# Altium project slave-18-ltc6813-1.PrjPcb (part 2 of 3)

## Sheet passive_balancing.SchDoc
size A3; SheetNumber: 5; SheetTotal: 15; SheetDescription: Passive Balancing
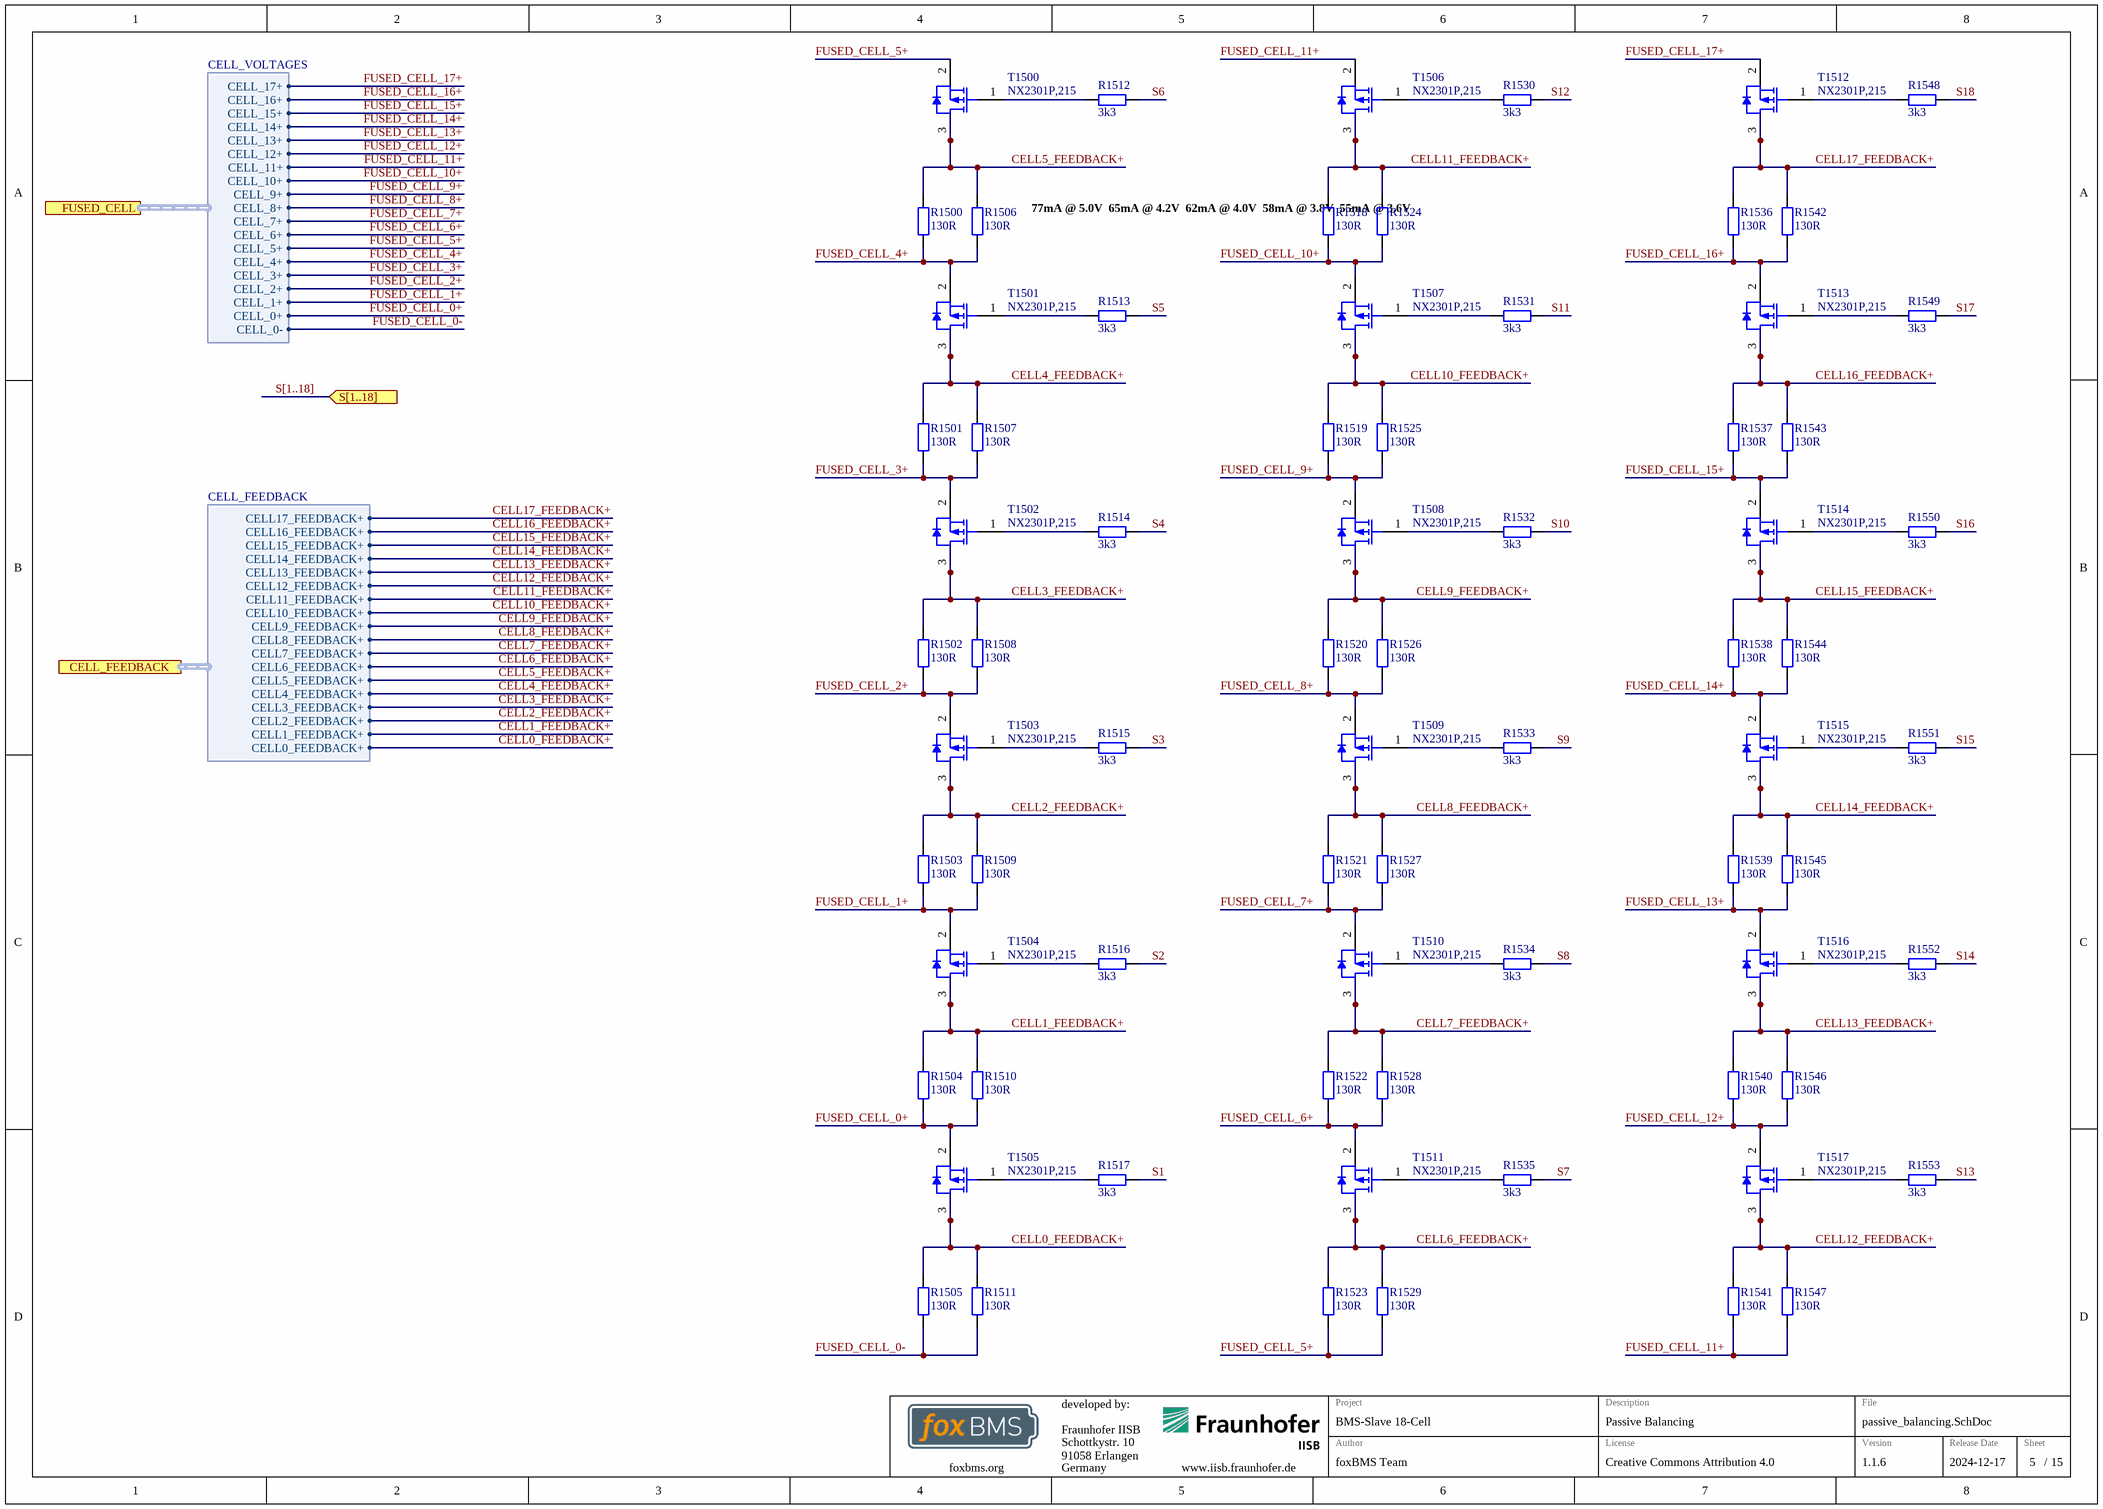
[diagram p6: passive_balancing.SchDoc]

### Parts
R1500  130R  [RESC5025X07N]
R1501  130R  [RESC5025X07N]
R1502  130R  [RESC5025X07N]
R1503  130R  [RESC5025X07N]
R1504  130R  [RESC5025X07N]
R1505  130R  [RESC5025X07N]
R1506  130R  [RESC5025X07N]
R1507  130R  [RESC5025X07N]
R1508  130R  [RESC5025X07N]
R1509  130R  [RESC5025X07N]
R1510  130R  [RESC5025X07N]
R1511  130R  [RESC5025X07N]
R1512  3k3  [RESC1608X05N]
R1513  3k3  [RESC1608X05N]
R1514  3k3  [RESC1608X05N]
R1515  3k3  [RESC1608X05N]
R1516  3k3  [RESC1608X05N]
R1517  3k3  [RESC1608X05N]
R1518  130R  [RESC5025X07N]
R1519  130R  [RESC5025X07N]
R1520  130R  [RESC5025X07N]
R1521  130R  [RESC5025X07N]
R1522  130R  [RESC5025X07N]
R1523  130R  [RESC5025X07N]
R1524  130R  [RESC5025X07N]
R1525  130R  [RESC5025X07N]
R1526  130R  [RESC5025X07N]
R1527  130R  [RESC5025X07N]
R1528  130R  [RESC5025X07N]
R1529  130R  [RESC5025X07N]
R1530  3k3  [RESC1608X05N]
R1531  3k3  [RESC1608X05N]
R1532  3k3  [RESC1608X05N]
R1533  3k3  [RESC1608X05N]
R1534  3k3  [RESC1608X05N]
R1535  3k3  [RESC1608X05N]
R1536  130R  [RESC5025X07N]
R1537  130R  [RESC5025X07N]
R1538  130R  [RESC5025X07N]
R1539  130R  [RESC5025X07N]
R1540  130R  [RESC5025X07N]
R1541  130R  [RESC5025X07N]
R1542  130R  [RESC5025X07N]
R1543  130R  [RESC5025X07N]
R1544  130R  [RESC5025X07N]
R1545  130R  [RESC5025X07N]
R1546  130R  [RESC5025X07N]
R1547  130R  [RESC5025X07N]
R1548  3k3  [RESC1608X05N]
R1549  3k3  [RESC1608X05N]
R1550  3k3  [RESC1608X05N]
R1551  3k3  [RESC1608X05N]
R1552  3k3  [RESC1608X05N]
R1553  3k3  [RESC1608X05N]
T1500  NX2301P,215  [NXP-SOT23_N]
T1501  NX2301P,215  [NXP-SOT23_N]
T1502  NX2301P,215  [NXP-SOT23_N]
T1503  NX2301P,215  [NXP-SOT23_N]
T1504  NX2301P,215  [NXP-SOT23_N]
T1505  NX2301P,215  [NXP-SOT23_N]
T1506  NX2301P,215  [NXP-SOT23_N]
T1507  NX2301P,215  [NXP-SOT23_N]
T1508  NX2301P,215  [NXP-SOT23_N]
T1509  NX2301P,215  [NXP-SOT23_N]
T1510  NX2301P,215  [NXP-SOT23_N]
T1511  NX2301P,215  [NXP-SOT23_N]
T1512  NX2301P,215  [NXP-SOT23_N]
T1513  NX2301P,215  [NXP-SOT23_N]
T1514  NX2301P,215  [NXP-SOT23_N]
T1515  NX2301P,215  [NXP-SOT23_N]
T1516  NX2301P,215  [NXP-SOT23_N]
T1517  NX2301P,215  [NXP-SOT23_N]

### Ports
CELL_FEEDBACK (harness CELL_FEEDBACK), FUSED_CELL (harness CELL_VOLTAGES), S[1..18] (in)

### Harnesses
CELL_FEEDBACK: CELL11_FEEDBACK+, CELL10_FEEDBACK+, CELL9_FEEDBACK+, CELL8_FEEDBACK+, CELL7_FEEDBACK+, CELL6_FEEDBACK+, CELL5_FEEDBACK+, CELL4_FEEDBACK+, CELL3_FEEDBACK+, CELL2_FEEDBACK+, CELL1_FEEDBACK+, CELL0_FEEDBACK+, CELL12_FEEDBACK+, CELL13_FEEDBACK+, CELL14_FEEDBACK+, CELL15_FEEDBACK+, CELL16_FEEDBACK+, CELL17_FEEDBACK+
CELL_VOLTAGES: CELL_0-, CELL_0+, CELL_1+, CELL_10+, CELL_11+, CELL_12+, CELL_13+, CELL_14+, CELL_15+, CELL_16+, CELL_17+, CELL_2+, CELL_3+, CELL_4+, CELL_5+, CELL_6+, CELL_7+, CELL_8+, CELL_9+

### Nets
CELL0_FEEDBACK+: R1505.2 R1511.2 T1505.3(D) ; port CELL_FEEDBACK.CELL0_FEEDBACK+  [project net CELL_FEEDBACK.CELL0_FEEDBACK+]
CELL1_FEEDBACK+: R1504.2 R1510.2 T1504.3(D) ; port CELL_FEEDBACK.CELL1_FEEDBACK+  [project net CELL_FEEDBACK.CELL1_FEEDBACK+]
CELL2_FEEDBACK+: R1503.2 R1509.2 T1503.3(D) ; port CELL_FEEDBACK.CELL2_FEEDBACK+  [project net CELL_FEEDBACK.CELL2_FEEDBACK+]
CELL3_FEEDBACK+: R1502.2 R1508.2 T1502.3(D) ; port CELL_FEEDBACK.CELL3_FEEDBACK+  [project net CELL_FEEDBACK.CELL3_FEEDBACK+]
CELL4_FEEDBACK+: R1501.2 R1507.2 T1501.3(D) ; port CELL_FEEDBACK.CELL4_FEEDBACK+  [project net CELL_FEEDBACK.CELL4_FEEDBACK+]
CELL5_FEEDBACK+: R1500.2 R1506.2 T1500.3(D) ; port CELL_FEEDBACK.CELL5_FEEDBACK+  [project net CELL_FEEDBACK.CELL5_FEEDBACK+]
CELL6_FEEDBACK+: R1523.2 R1529.2 T1511.3(D) ; port CELL_FEEDBACK.CELL6_FEEDBACK+  [project net CELL_FEEDBACK.CELL6_FEEDBACK+]
CELL7_FEEDBACK+: R1522.2 R1528.2 T1510.3(D) ; port CELL_FEEDBACK.CELL7_FEEDBACK+  [project net CELL_FEEDBACK.CELL7_FEEDBACK+]
CELL8_FEEDBACK+: R1521.2 R1527.2 T1509.3(D) ; port CELL_FEEDBACK.CELL8_FEEDBACK+  [project net CELL_FEEDBACK.CELL8_FEEDBACK+]
CELL9_FEEDBACK+: R1520.2 R1526.2 T1508.3(D) ; port CELL_FEEDBACK.CELL9_FEEDBACK+  [project net CELL_FEEDBACK.CELL9_FEEDBACK+]
CELL10_FEEDBACK+: R1519.2 R1525.2 T1507.3(D) ; port CELL_FEEDBACK.CELL10_FEEDBACK+  [project net CELL_FEEDBACK.CELL10_FEEDBACK+]
CELL11_FEEDBACK+: R1518.2 R1524.2 T1506.3(D) ; port CELL_FEEDBACK.CELL11_FEEDBACK+  [project net CELL_FEEDBACK.CELL11_FEEDBACK+]
CELL12_FEEDBACK+: R1541.2 R1547.2 T1517.3(D) ; port CELL_FEEDBACK.CELL12_FEEDBACK+  [project net CELL_FEEDBACK.CELL12_FEEDBACK+]
CELL13_FEEDBACK+: R1540.2 R1546.2 T1516.3(D) ; port CELL_FEEDBACK.CELL13_FEEDBACK+  [project net CELL_FEEDBACK.CELL13_FEEDBACK+]
CELL14_FEEDBACK+: R1539.2 R1545.2 T1515.3(D) ; port CELL_FEEDBACK.CELL14_FEEDBACK+  [project net CELL_FEEDBACK.CELL14_FEEDBACK+]
CELL15_FEEDBACK+: R1538.2 R1544.2 T1514.3(D) ; port CELL_FEEDBACK.CELL15_FEEDBACK+  [project net CELL_FEEDBACK.CELL15_FEEDBACK+]
CELL16_FEEDBACK+: R1537.2 R1543.2 T1513.3(D) ; port CELL_FEEDBACK.CELL16_FEEDBACK+  [project net CELL_FEEDBACK.CELL16_FEEDBACK+]
CELL17_FEEDBACK+: R1536.2 R1542.2 T1512.3(D) ; port CELL_FEEDBACK.CELL17_FEEDBACK+  [project net CELL_FEEDBACK.CELL17_FEEDBACK+]
FUSED_CELL_0+: R1504.1 R1510.1 T1505.2(S) ; port FUSED_CELL.CELL_0+  [project net FUSED_CELL.CELL_0+]
FUSED_CELL_0-: R1505.1 R1511.1 ; port FUSED_CELL.CELL_0-  [project net FUSED_CELL.CELL_0-]
FUSED_CELL_1+: R1503.1 R1509.1 T1504.2(S) ; port FUSED_CELL.CELL_1+  [project net FUSED_CELL.CELL_1+]
FUSED_CELL_2+: R1502.1 R1508.1 T1503.2(S) ; port FUSED_CELL.CELL_2+  [project net FUSED_CELL.CELL_2+]
FUSED_CELL_3+: R1501.1 R1507.1 T1502.2(S) ; port FUSED_CELL.CELL_3+  [project net FUSED_CELL.CELL_3+]
FUSED_CELL_4+: R1500.1 R1506.1 T1501.2(S) ; port FUSED_CELL.CELL_4+  [project net FUSED_CELL.CELL_4+]
FUSED_CELL_5+: R1523.1 R1529.1 T1500.2(S) ; port FUSED_CELL.CELL_5+  [project net FUSED_CELL.CELL_5+]
FUSED_CELL_6+: R1522.1 R1528.1 T1511.2(S) ; port FUSED_CELL.CELL_6+  [project net FUSED_CELL.CELL_6+]
FUSED_CELL_7+: R1521.1 R1527.1 T1510.2(S) ; port FUSED_CELL.CELL_7+  [project net FUSED_CELL.CELL_7+]
FUSED_CELL_8+: R1520.1 R1526.1 T1509.2(S) ; port FUSED_CELL.CELL_8+  [project net FUSED_CELL.CELL_8+]
FUSED_CELL_9+: R1519.1 R1525.1 T1508.2(S) ; port FUSED_CELL.CELL_9+  [project net FUSED_CELL.CELL_9+]
FUSED_CELL_10+: R1518.1 R1524.1 T1507.2(S) ; port FUSED_CELL.CELL_10+  [project net FUSED_CELL.CELL_10+]
FUSED_CELL_11+: R1541.1 R1547.1 T1506.2(S) ; port FUSED_CELL.CELL_11+  [project net FUSED_CELL.CELL_11+]
FUSED_CELL_12+: R1540.1 R1546.1 T1517.2(S) ; port FUSED_CELL.CELL_12+  [project net FUSED_CELL.CELL_12+]
FUSED_CELL_13+: R1539.1 R1545.1 T1516.2(S) ; port FUSED_CELL.CELL_13+  [project net FUSED_CELL.CELL_13+]
FUSED_CELL_14+: R1538.1 R1544.1 T1515.2(S) ; port FUSED_CELL.CELL_14+  [project net FUSED_CELL.CELL_14+]
FUSED_CELL_15+: R1537.1 R1543.1 T1514.2(S) ; port FUSED_CELL.CELL_15+  [project net FUSED_CELL.CELL_15+]
FUSED_CELL_16+: R1536.1 R1542.1 T1513.2(S) ; port FUSED_CELL.CELL_16+  [project net FUSED_CELL.CELL_16+]
FUSED_CELL_17+: T1512.2(S) ; port FUSED_CELL.CELL_17+  [project net FUSED_CELL.CELL_17+]
S1: R1517.2  [project net PRIMARY-S1]
S2: R1516.2  [project net PRIMARY-S2]
S3: R1515.2  [project net PRIMARY-S3]
S4: R1514.2  [project net PRIMARY-S4]
S5: R1513.2  [project net PRIMARY-S5]
S6: R1512.2  [project net PRIMARY-S6]
S7: R1535.2  [project net PRIMARY-S7]
S8: R1534.2  [project net PRIMARY-S8]
S9: R1533.2  [project net PRIMARY-S9]
S10: R1532.2  [project net PRIMARY-S10]
S11: R1531.2  [project net PRIMARY-S11]
S12: R1530.2  [project net PRIMARY-S12]
S13: R1553.2  [project net PRIMARY-S13]
S14: R1552.2  [project net PRIMARY-S14]
S15: R1551.2  [project net PRIMARY-S15]
S16: R1550.2  [project net PRIMARY-S16]
S17: R1549.2  [project net PRIMARY-S17]
S18: R1548.2  [project net PRIMARY-S18]
NetR1512_1: R1512.1 T1500.1(G)
NetR1513_1: R1513.1 T1501.1(G)
NetR1514_1: R1514.1 T1502.1(G)
NetR1515_1: R1515.1 T1503.1(G)
NetR1516_1: R1516.1 T1504.1(G)
NetR1517_1: R1517.1 T1505.1(G)
NetR1530_1: R1530.1 T1506.1(G)
NetR1531_1: R1531.1 T1507.1(G)
NetR1532_1: R1532.1 T1508.1(G)
NetR1533_1: R1533.1 T1509.1(G)
NetR1534_1: R1534.1 T1510.1(G)
NetR1535_1: R1535.1 T1511.1(G)
NetR1548_1: R1548.1 T1512.1(G)
NetR1549_1: R1549.1 T1513.1(G)
NetR1550_1: R1550.1 T1514.1(G)
NetR1551_1: R1551.1 T1515.1(G)
NetR1552_1: R1552.1 T1516.1(G)
NetR1553_1: R1553.1 T1517.1(G)

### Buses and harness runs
bus S[1..18] = port S[1..18]

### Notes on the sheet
- 77mA @ 5.0V
  65mA @ 4.2V
  62mA @ 4.0V
  58mA @ 3.8V
  55mA @ 3.6V

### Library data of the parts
R1500-R1511 R1518-R1529 R1536-R1547 = gen_R_130R_2010: SMD Resistor 130R 2010; Tolerance: 5%; Power: 0.75W; Case EIA: 2010; Case Metric: 5025; Maximum Working Voltage: 400V; PnP Package: R_2010; Automotive Qualified: True
R1512-R1517 R1530-R1535 R1548-R1553 = gen_R_3k3_0603: SMD Resistor 3k3 0603; Tolerance: 1%; Power: 0.1W; Case EIA: 0603; Case Metric: 1608; Maximum Working Voltage: 75V; PnP Package: R_0603; Automotive Qualified: True
T1500-T1517 = CMP-1259-00090-1: P-Channel Trench MOSFET, -20 V, -2 A, -55 to 150 degC, 3-Pin SOT23, Tape and Reel; Manufacturer: NXP Semiconductors; VGSth [typ] (V): -0.75; Channel Type: P; Packing: Tape & Reel; Automotive Qualified: Y; IDM [max] (A): -6

## Sheet LTC.SchDoc
size A3; SheetNumber: 2; SheetTotal: 15; SheetDescription: LTC6813
Used 2 times, as channels U_primary_LTC, U_secondary_LTC. Parts and nets are listed once, with the designators drawn on the sheet.
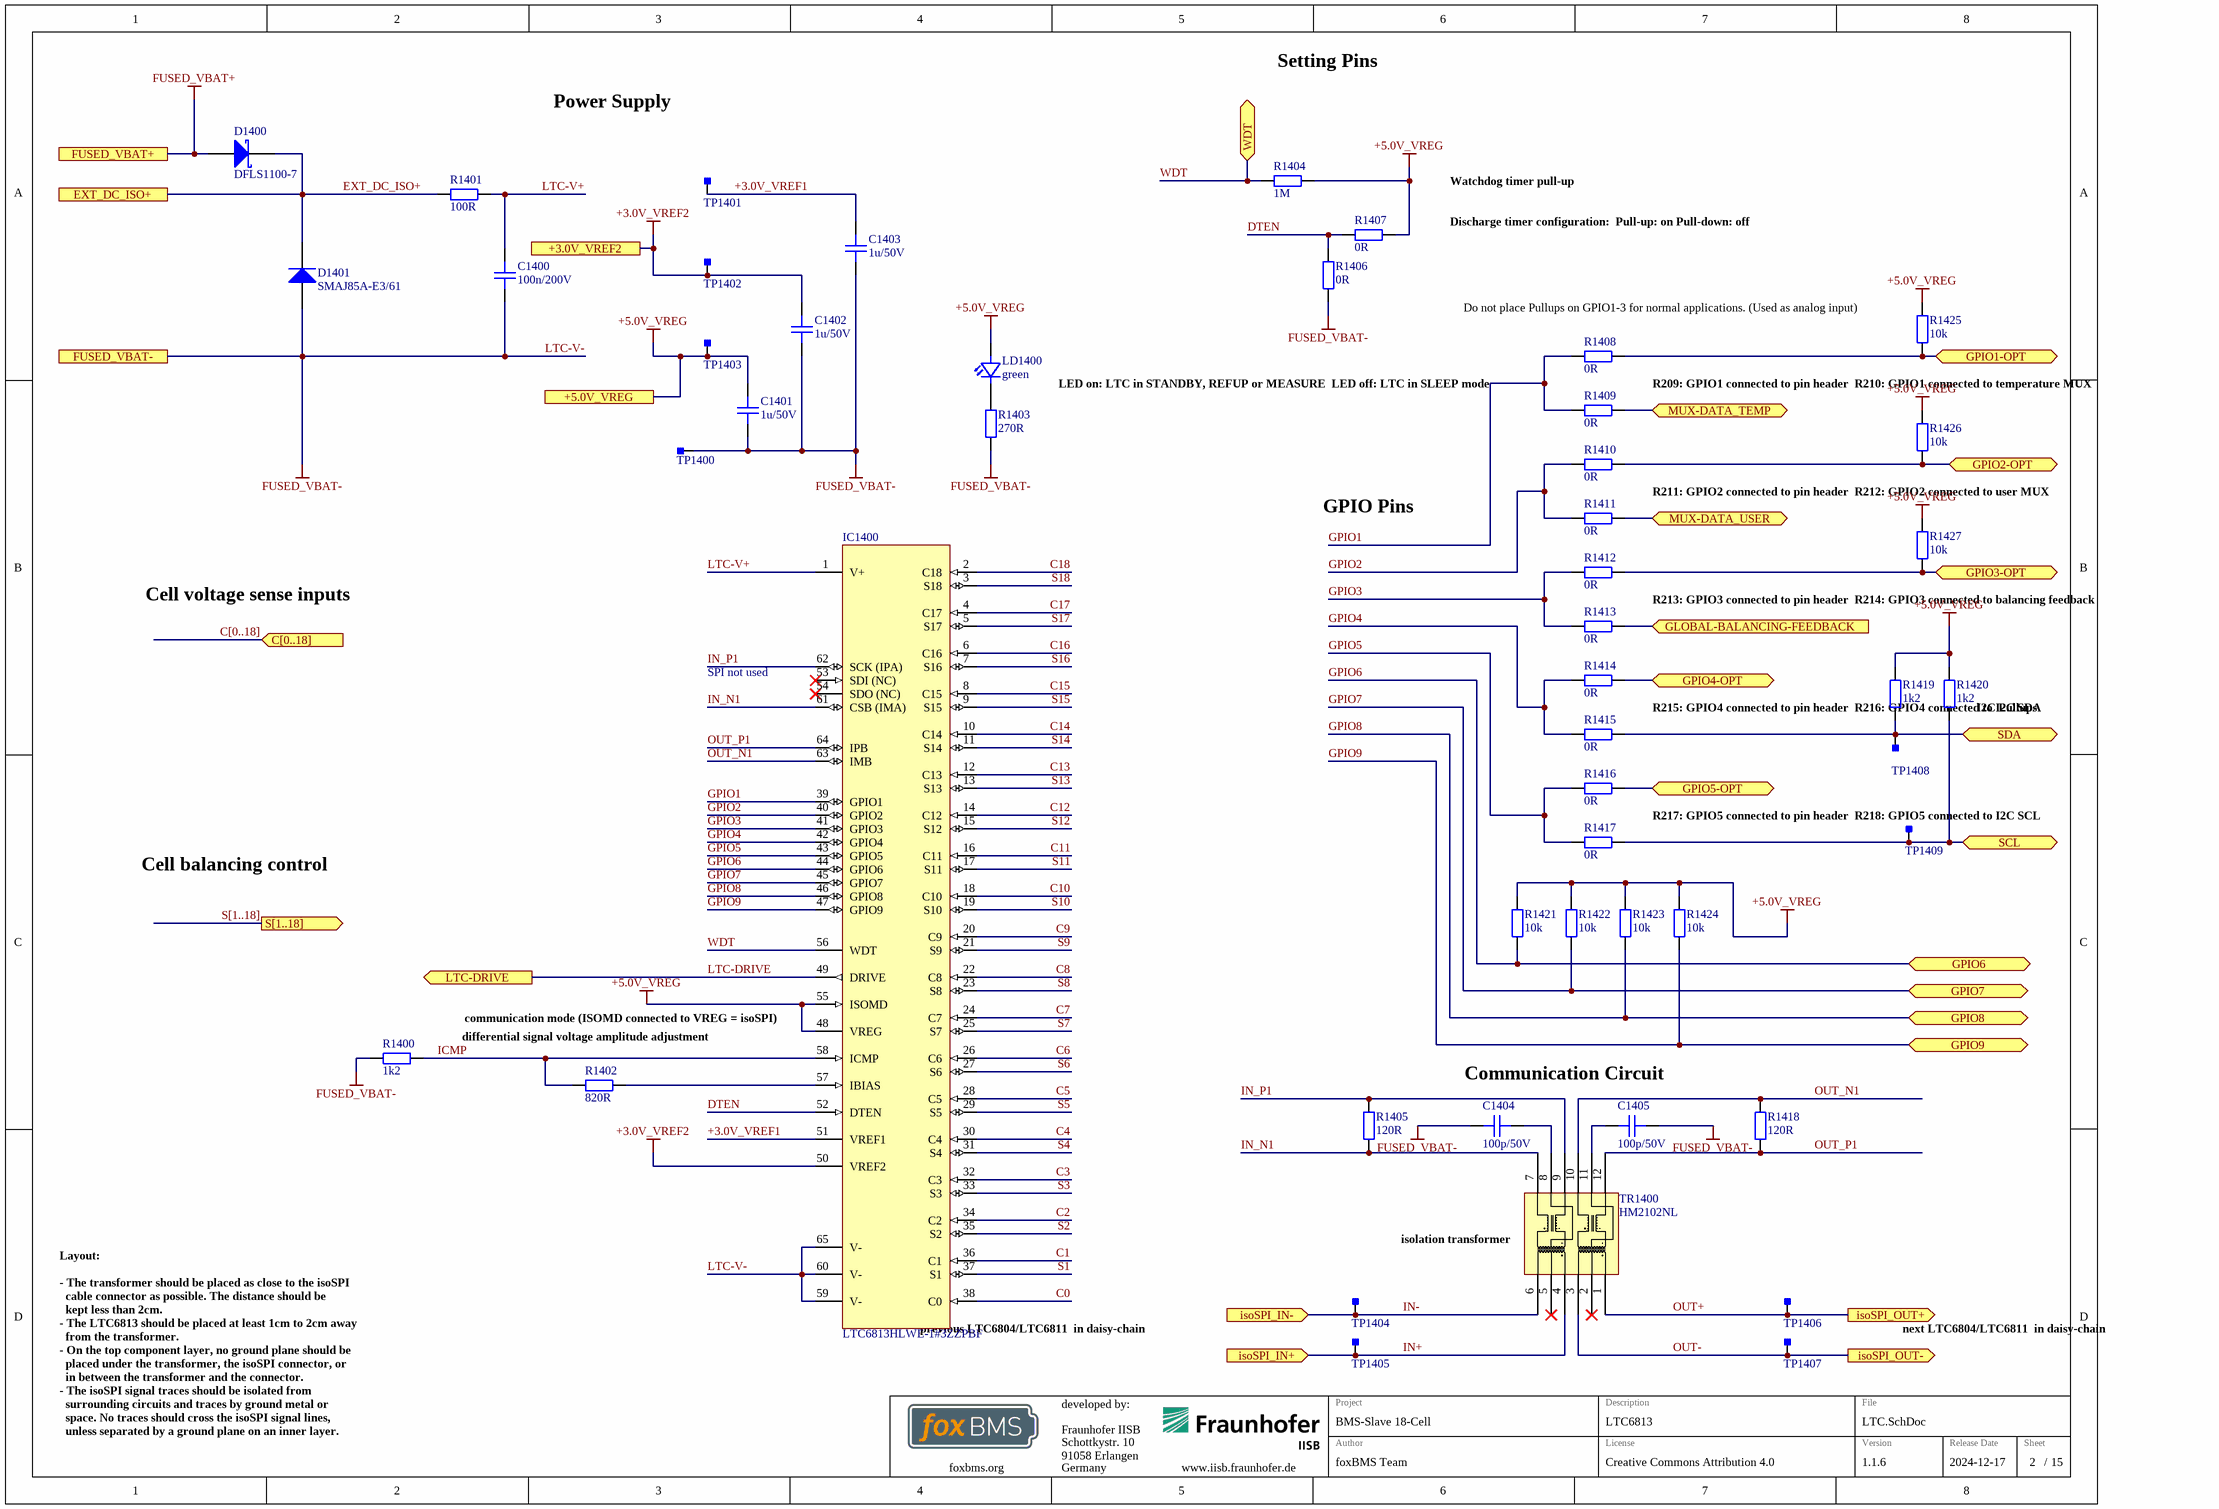
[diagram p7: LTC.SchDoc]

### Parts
C1400  100n/200V  [CAPC3216X18N]
C1401  1u/50V  [CAPC2012X14N]
C1402  1u/50V  [CAPC2012X14N]
C1403  1u/50V  [CAPC2012X14N]
C1404  100p/50V  [CAPC1608X08N]
C1405  100p/50V  [CAPC1608X08N]
D1400  DFLS1100-7  [DIOD-POWERDI123-2_V]
D1401  SMAJ85A-E3/61  [VISH-DO-214AC-2_L]
IC1400  LTC6813HLWE-1#3ZZPBF  [TSQFP50P1200X1200X160_HS-65N]
LD1400  green  [LEDC1608X07N]
R1400  1k2  [RESC1608X05N]
R1401  100R  [RESC2012X05N]
R1402  820R  [RESC1608X05N]
R1403  270R  [RESC1608X05N]
R1404  1M  [RESC1608X05N]
R1405  120R  [RESC1608X05N]
R1406  0R  [RESC1608X05N]
R1407  0R  [RESC1608X05N]
R1408  0R  [RESC1608X05N]
R1409  0R  [RESC1608X05N]
R1410  0R  [RESC1608X05N]
R1411  0R  [RESC1608X05N]
R1412  0R  [RESC1608X05N]
R1413  0R  [RESC1608X05N]
R1414  0R  [RESC1608X05N]
R1415  0R  [RESC1608X05N]
R1416  0R  [RESC1608X05N]
R1417  0R  [RESC1608X05N]
R1418  120R  [RESC1608X05N]
R1419  1k2  [RESC1608X05N]
R1420  1k2  [RESC1608X05N]
R1421  10k  [RESC1608X05N]
R1422  10k  [RESC1608X05N]
R1423  10k  [RESC1608X05N]
R1424  10k  [RESC1608X05N]
R1425  10k  [RESC1608X05N]
R1426  10k  [RESC1608X05N]
R1427  10k  [RESC1608X05N]
TP1400  Testpoint_Square  [Testpoint_S1]  (value not drawn)  (no BOM)
TP1401  Testpoint_Square  [Testpoint_S1]  (value not drawn)  (no BOM)
TP1402  Testpoint_Square  [Testpoint_S1]  (value not drawn)  (no BOM)
TP1403  Testpoint_Square  [Testpoint_S1]  (value not drawn)  (no BOM)
TP1404  Testpoint_Square  [Testpoint_S1]  (value not drawn)  (no BOM)
TP1405  Testpoint_Square  [Testpoint_S1]  (value not drawn)  (no BOM)
TP1406  Testpoint_Square  [Testpoint_S1]  (value not drawn)  (no BOM)
TP1407  Testpoint_Square  [Testpoint_S1]  (value not drawn)  (no BOM)
TP1408  Testpoint_Square  [Testpoint_S1]  (value not drawn)  (no BOM)
TP1409  Testpoint_Square  [Testpoint_S1]  (value not drawn)  (no BOM)
TR1400  HM2102NL  [HM2102NL]

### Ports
+3.0V_VREF2, +5.0V_VREG, C[0..18] (in), EXT_DC_ISO+, FUSED_VBAT+, FUSED_VBAT-, GLOBAL-BALANCING-FEEDBACK (in), GPIO1-OPT (bidir), GPIO2-OPT (bidir), GPIO3-OPT (bidir), GPIO4-OPT (bidir), GPIO5-OPT (bidir), GPIO6 (bidir), GPIO7 (bidir), GPIO8 (bidir), GPIO9 (bidir), isoSPI_IN+ (in), isoSPI_IN- (in), isoSPI_OUT+ (out), isoSPI_OUT- (out), LTC-DRIVE (out), MUX-DATA_TEMP (bidir), MUX-DATA_USER (bidir), S[1..18] (out), SCL (bidir), SDA (bidir), WDT (bidir)

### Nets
+3.0V_VREF2: C1402.2 IC1400.50(VREF2) TP1402.1 ; port +3.0V_VREF2
+5.0V_VREG: C1401.2 IC1400.48(VREG) IC1400.55(ISOMD) LD1400.2(A) R1404.2 R1407.2 R1419.2 R1420.2 R1421.2 R1422.2 R1423.2 R1424.2 R1425.2 R1426.2 R1427.2 TP1403.1 ; port +5.0V_VREG
FUSED_VBAT+: D1400.1(A) ; port FUSED_VBAT+
FUSED_VBAT-: C1400.2 C1401.1 C1402.1 C1403.1 C1404.1 C1405.1 D1401.2(A) IC1400.59(V-) IC1400.60(V-) IC1400.65(V-) R1400.1 R1403.1 R1406.1 TP1400.1 ; port FUSED_VBAT-  [also labelled LTC-V-]
+3.0V_VREF1: C1403.2 IC1400.51(VREF1) TP1401.1
C0: IC1400.38(C0)
C1: IC1400.36(C1)
C2: IC1400.34(C2)
C3: IC1400.32(C3)
C4: IC1400.30(C4)
C5: IC1400.28(C5)
C6: IC1400.26(C6)
C7: IC1400.24(C7)
C8: IC1400.22(C8)
C9: IC1400.20(C9)
C10: IC1400.18(C10)
C11: IC1400.16(C11)
C12: IC1400.14(C12)
C13: IC1400.12(C13)
C14: IC1400.10(C14)
C15: IC1400.8(C15)
C16: IC1400.6(C16)
C17: IC1400.4(C17)
C18: IC1400.2(C18)
DTEN: IC1400.52(DTEN) R1406.2 R1407.1
EXT_DC_ISO+: D1400.2(K) D1401.1(K) R1401.1 ; port EXT_DC_ISO+
GLOBAL-BALANCING-FEEDBACK: R1413.1 ; port GLOBAL-BALANCING-FEEDBACK
GPIO1: IC1400.39(GPIO1) R1408.2 R1409.2
GPIO1-OPT: R1408.1 R1425.1 ; port GPIO1-OPT
GPIO2: IC1400.40(GPIO2) R1410.2 R1411.2
GPIO2-OPT: R1410.1 R1426.1 ; port GPIO2-OPT
GPIO3: IC1400.41(GPIO3) R1412.2 R1413.2
GPIO3-OPT: R1412.1 R1427.1 ; port GPIO3-OPT
GPIO4: IC1400.42(GPIO4) R1414.2 R1415.2
GPIO4-OPT: R1414.1 ; port GPIO4-OPT
GPIO5: IC1400.43(GPIO5) R1416.2 R1417.2
GPIO5-OPT: R1416.1 ; port GPIO5-OPT
GPIO6: IC1400.44(GPIO6) R1421.1 ; port GPIO6
GPIO7: IC1400.45(GPIO7) R1422.1 ; port GPIO7
GPIO8: IC1400.46(GPIO8) R1423.1 ; port GPIO8
GPIO9: IC1400.47(GPIO9) R1424.1 ; port GPIO9
ICMP: IC1400.58(ICMP) R1400.2 R1402.1
IN+: TP1405.1 TR1400.4 ; port isoSPI_IN+
IN-: TP1404.1 TR1400.6 ; port isoSPI_IN-
IN_N1: IC1400.61(CSB_(IMA)) R1405.2 TR1400.7
IN_P1: IC1400.62(SCK_(IPA)) R1405.1 TR1400.9
LTC-DRIVE: IC1400.49(DRIVE) ; port LTC-DRIVE
LTC-V+: C1400.1 IC1400.1(V+) R1401.2
MUX-DATA_TEMP: R1409.1 ; port MUX-DATA_TEMP
MUX-DATA_USER: R1411.1 ; port MUX-DATA_USER
OUT+: TP1406.1 TR1400.1 ; port isoSPI_OUT+
OUT-: TP1407.1 TR1400.3 ; port isoSPI_OUT-
OUT_N1: IC1400.63(IMB) R1418.2 TR1400.10
OUT_P1: IC1400.64(IPB) R1418.1 TR1400.12
S1: IC1400.37(S1)
S2: IC1400.35(S2)
S3: IC1400.33(S3)
S4: IC1400.31(S4)
S5: IC1400.29(S5)
S6: IC1400.27(S6)
S7: IC1400.25(S7)
S8: IC1400.23(S8)
S9: IC1400.21(S9)
S10: IC1400.19(S10)
S11: IC1400.17(S11)
S12: IC1400.15(S12)
S13: IC1400.13(S13)
S14: IC1400.11(S14)
S15: IC1400.9(S15)
S16: IC1400.7(S16)
S17: IC1400.5(S17)
S18: IC1400.3(S18)
SCL: R1417.1 R1420.1 TP1409.1 ; port SCL
SDA: R1415.1 R1419.1 TP1408.1 ; port SDA
WDT: IC1400.56(WDT) R1404.1 ; port WDT
NetC1404_2: C1404.2 TR1400.8
NetC1405_2: C1405.2 TR1400.11
NetIC1400_57: IC1400.57(IBIAS) R1402.2
NetLD1400_1: LD1400.1(C) R1403.2

Not connected (* = marked no-connect by the designer): IC1400 53(SDI_(NC))* 54(SDO_(NC))*; TR1400 2* 5*

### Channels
U_primary_LTC: designators end in _1; ports +3.0V_VREF2=+3.0V_VREF2 +5.0V_VREG=+5.0V_VREG EXT_DC_ISO+=EXT_DC_ISO+ FUSED_VBAT+=FUSED_VBAT+ FUSED_VBAT-=FUSED_VBAT- GLOBAL-BALANCING-FEEDBACK=GLOBAL-BAL-FB GPIO1-OPT=PRIMARY-GPIO1-OPT GPIO2-OPT=PRIMARY-GPIO2-OPT GPIO3-OPT=PRIMARY-GPIO3-OPT GPIO4-OPT=PRIMARY-GPIO4-OPT GPIO5-OPT=PRIMARY-GPIO5-OPT GPIO6=PRIMARY-GPIO6 GPIO7=PRIMARY-GPIO7 GPIO8=PRIMARY-GPIO8 GPIO9=PRIMARY-GPIO9 isoSPI_IN+=PRIMARY-IN+ isoSPI_IN-=PRIMARY-IN- isoSPI_OUT+=PRIMARY-OUT+ isoSPI_OUT-=PRIMARY-OUT- LTC-DRIVE=PRIMARY-LTC-DRIVE MUX-DATA_TEMP=PRIMARY-MUX-DATA_TEMP MUX-DATA_USER=PRIMARY-MUX-DATA_USER SCL=PRIMARY-SCL SDA=PRIMARY-SDA WDT=PRIMARY-WDT
U_secondary_LTC: designators end in _2; ports +3.0V_VREF2=+3.0V_VREF2 +5.0V_VREG=+5.0V_VREG EXT_DC_ISO+=EXT_DC_ISO+ FUSED_VBAT+=FUSED_VBAT+ FUSED_VBAT-=FUSED_VBAT- GLOBAL-BALANCING-FEEDBACK=GLOBAL-BAL-FB GPIO1-OPT=SECONDARY-GPIO1-OPT GPIO2-OPT=SECONDARY-GPIO2-OPT GPIO3-OPT=SECONDARY-GPIO3-OPT GPIO4-OPT=SECONDARY-GPIO4-OPT GPIO5-OPT=SECONDARY-GPIO5-OPT GPIO6=SECONDARY-GPIO6 GPIO7=SECONDARY-GPIO7 GPIO8=SECONDARY-GPIO8 GPIO9=SECONDARY-GPIO9 isoSPI_IN+=SECONDARY-IN+ isoSPI_IN-=SECONDARY-IN- isoSPI_OUT+=SECONDARY-OUT+ isoSPI_OUT-=SECONDARY-OUT- LTC-DRIVE=SECONDARY-LTC-DRIVE MUX-DATA_TEMP=SECONDARY-MUX-DATA_TEMP MUX-DATA_USER=SECONDARY-MUX-DATA_USER SCL=SECONDARY-SCL SDA=SECONDARY-SDA WDT=SECONDARY-WDT

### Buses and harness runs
bus C[0..18] = port C[0..18]
bus S[1..18] = port S[1..18]

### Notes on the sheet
- Power Supply
- Setting Pins
- Watchdog timer pull-up
- Discharge timer configuration:
  Pull-up: on
  Pull-down: off
- (near R1425) Do not place Pullups on GPIO1-3 for normal applications. (Used as analog input)
- LED on: LTC in STANDBY, REFUP or MEASURE
  LED off: LTC in SLEEP mode
- R209: GPIO1 connected to pin header
  R210: GPIO1 connected to temperature MUX
- GPIO Pins
- R211: GPIO2 connected to pin header
  R212: GPIO2 connected to user MUX
- Cell voltage sense inputs
- R213: GPIO3 connected to pin header
  R214: GPIO3 connected to balancing feedback
- SPI not used
- R215: GPIO4 connected to pin header
  R216: GPIO4 connected to I2C SDA
- (near R1420) I2C Pullups
- (near TP1409) R217: GPIO5 connected to pin header
  R218: GPIO5 connected to I2C SCL
- Cell balancing control
- communication mode (ISOMD connected to VREG = isoSPI)
- differential signal voltage amplitude adjustment
- Communication Circuit
- (near TR1400) isolation transformer
- (near TP1405) previous LTC6804/LTC6811
  in daisy-chain
- next LTC6804/LTC6811
  in daisy-chain
- Layout:
  - The transformer should be placed as close to the isoSPI
  cable connector as possible. The distance should be
  kept less than 2cm.
  - The LTC6813 should be placed at least 1cm to 2cm away
  from the transformer.
  - On the top component layer, no ground plane should be
  placed under the transformer, the isoSPI connector, or
  in between the transformer and the connector.
  - The isoSPI signal traces should be isolated from
  surrounding circuits and traces by ground metal or
  space. No traces should cross the isoSPI signal lines,
  unless separated by a ground plane on an inner layer.

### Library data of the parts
C1400 = gen_C_ceramic_100n_200V_X7R_1206: MLCC; Capacitance: 100n; Rated Voltage: 200V; Dielectric: X7R; Case EIA: 1206; Case Metric: 3216; Automotive Qualified: True
C1401-C1403 = gen_C_ceramic_1u_50V_X7R_0805: MLCC; Capacitance: 1u; Rated Voltage: 50V; Dielectric: X7R; Case EIA: 0805; Case Metric: 2012; Automotive Qualified: True; Tolerance: ± 10%; AVT Set: x
C1404 C1405 = gen_C_ceramic_100p_50V_C0G_0603: MLCC; Capacitance: 100p; Rated Voltage: 50V; Dielectric: C0G; Case EIA: 0603; Case Metric: 1608; Automotive Qualified: True; Tolerance: ± 10%
D1400 = CMP-2000-05099-1: 1 A High Voltage Schottky Barrier Rectifier, 0.62 V, -55 to 175 degC, 2- Pin POWERDI123, Pb-Free, Tape and Reel; Manufacturer: Diodes Inc; Average Rectified Current-Max: 1A; Peak Current-Max: 40A; Forward Voltage: 0.77V; Reverse Current-Max: 1µA; Reverse Voltage-Max [Vrrm]: 100V
D1401 = CMP-0548-00243-2: Transient Voltage Suppressor, 6.40 to 231 V, 85 V Stand-off Voltage, Uni-Directional, -55 to 155 degC, 2-pin DO-214AC, Pb-Free, Tape and Reel; Manufacturer: Vishay Semiconductor; VWM (V): 85; PPPM (W): 400, 300; VBR Uni-Directional (V): 6.4 to 231; IFSM: 40 A; ID (uA): 1
IC1400 = LTC6813HLWE-1#3ZZPBF: 18 Cell Multicell Battery Monitor, -40 to 125 degC, Pb-Free; PartNumber: LTC6811HG-1#PBF; Manufacturer: Linear Technology; Type of Charger: Battery Stack Monitor; Vin Max(V): 60; Battery Chemistry: Li-Ion, Li-Polymer, NiMH; Number of Cells: > 1000 V of stacked Li-Ion cells; Automotive Qualified: True; PnP Package: QFP-64
LD1400 = LED_0603_green_AECQ: TLMG1100-GS08; Manufacturer: Vishay; Breakdown Voltage: 5V; Continuous Forward Current: 20mA; Forward Voltage @ 20mA: 2.1V; Automotive Qualified: True
R1400 R1419 R1420 = gen_R_1k2_0603: SMD Resistor 1k2 0603; Tolerance: 1%; Power: 0.1W; Case EIA: 0603; Case Metric: 1608; Maximum Working Voltage: 75V; PnP Package: R_0603; Automotive Qualified: True
R1401 = gen_R_100R_0805: SMD Resistor 100R 0805; Tolerance: 1%; Power: 0.125W; Case EIA: 0805; Case Metric: 2012; Maximum Working Voltage: 150V; PnP Package: R_0805; Automotive Qualified: True
R1402 = gen_R_820R_0603: SMD Resistor 820R 0603; Tolerance: 1%; Power: 0.1W; Case EIA: 0603; Case Metric: 1608; Maximum Working Voltage: 75V; PnP Package: R_0603; Automotive Qualified: True
R1403 = gen_R_270R_0603: SMD Resistor 270R 0603; Tolerance: 1%; Power: 0.1W; Case EIA: 0603; Case Metric: 1608; Maximum Working Voltage: 75V; PnP Package: R_0603; Automotive Qualified: True
R1404 = gen_R_1M_0603: SMD Resistor 1M 0603; Tolerance: 1%; Power: 0.1W; Case EIA: 0603; Case Metric: 1608; Maximum Working Voltage: 75V; PnP Package: R_0603; Automotive Qualified: True
R1405 R1418 = gen_R_120R_0603: SMD Resistor 120R 0603; Tolerance: 1%; Power: 0.1W; Case EIA: 0603; Case Metric: 1608; Maximum Working Voltage: 75V; PnP Package: R_0603; Automotive Qualified: True
R1406-R1417 = gen_R_0R_0603: SMD Resistor 0R 0603; Power: 0.1W; Case EIA: 0603; Case Metric: 1608; Maximum Working Voltage: 75V; PnP Package: R_0603; Automotive Qualified: True
R1421-R1427 = gen_R_10k_0603: SMD Resistor 10k 0603; Tolerance: 1%; Power: 0.1W; Case EIA: 0603; Case Metric: 1608; Maximum Working Voltage: 75V; PnP Package: R_0603; Automotive Qualified: True
TP1400-TP1409 = Testpoint_Square: Testpoint, square
TR1400 = HM2102NL: Pulse HM2102NL BMS Transformer; Automotive Qualified: True

## Sheet digital_io.SchDoc
size A3; SheetNumber: 8; SheetTotal: 15; SheetDescription: Digital IO
Used 2 times, as channels U_secondary_digital_io, U_primary_digital_io. Parts and nets are listed once, with the designators drawn on the sheet.
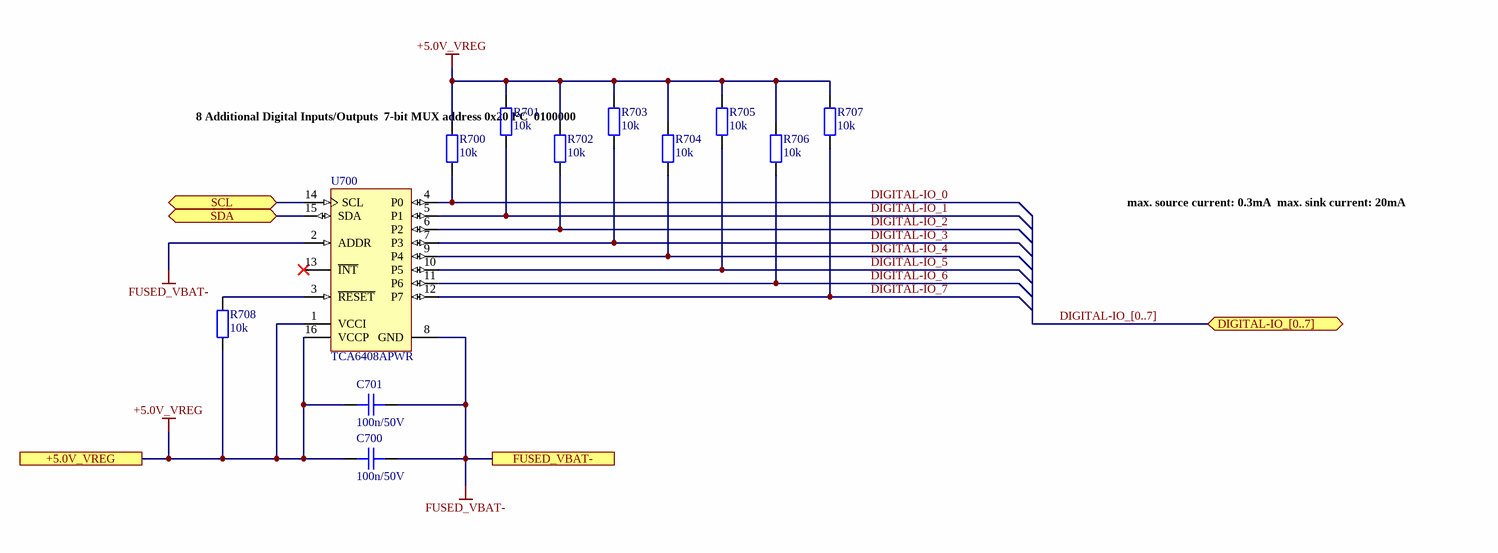
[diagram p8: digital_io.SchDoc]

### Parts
C700  100n/50V  [CAPC1608X08N]
C701  100n/50V  [CAPC1608X08N]
R700  10k  [RESC1608X05N]
R701  10k  [RESC1608X05N]
R702  10k  [RESC1608X05N]
R703  10k  [RESC1608X05N]
R704  10k  [RESC1608X05N]
R705  10k  [RESC1608X05N]
R706  10k  [RESC1608X05N]
R707  10k  [RESC1608X05N]
R708  10k  [RESC1608X05N]
U700  TCA6408APWR  [PW0016A_L]

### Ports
+5.0V_VREG, DIGITAL-IO_[0..7] (bidir), FUSED_VBAT-, SCL (bidir), SDA (bidir)

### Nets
+5.0V_VREG: C700.2 C701.2 R700.2 R701.2 R702.2 R703.2 R704.2 R705.2 R706.2 R707.2 R708.1 U700.1(VCCI) U700.16(VCCP) ; port +5.0V_VREG
FUSED_VBAT-: C700.1 C701.1 U700.2(ADDR) U700.8(GND) ; port FUSED_VBAT-
DIGITAL-IO_0: R700.1 U700.4(P0)
DIGITAL-IO_1: R701.1 U700.5(P1)
DIGITAL-IO_2: R702.1 U700.6(P2)
DIGITAL-IO_3: R703.1 U700.7(P3)
DIGITAL-IO_4: R704.1 U700.9(P4)
DIGITAL-IO_5: R705.1 U700.10(P5)
DIGITAL-IO_6: R706.1 U700.11(P6)
DIGITAL-IO_7: R707.1 U700.12(P7)
SCL: U700.14(SCL) ; port SCL
SDA: U700.15(SDA) ; port SDA
NetR708_2: R708.2 U700.3(~{RESET})

Not connected (* = marked no-connect by the designer): U700 13(~{INT})*

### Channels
U_secondary_digital_io: designators end in _1; ports +5.0V_VREG=+5.0V_VREG FUSED_VBAT-=FUSED_VBAT- SCL=SECONDARY-SCL SDA=SECONDARY-SDA
U_primary_digital_io: designators end in _2; ports +5.0V_VREG=+5.0V_VREG FUSED_VBAT-=FUSED_VBAT- SCL=PRIMARY-SCL SDA=PRIMARY-SDA

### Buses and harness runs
bus DIGITAL-IO_[0..7] = port DIGITAL-IO_[0..7]

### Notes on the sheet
- 8 Additional Digital Inputs/Outputs
  7-bit MUX address 0x20 I²C
  0100000
- max. source current: 0.3mA
  max. sink current: 20mA

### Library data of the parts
C700 C701 = gen_C_ceramic_100n_50V_X7R_0603: MLCC; Capacitance: 100n; Rated Voltage: 50V; Dielectric: X7R; Case EIA: 0603; Case Metric: 1608; PnP Package: C_0603_10; PnP Value: 100n/50V/X7R; PnP equipped: x; Automotive Qualified: True
R700-R708 = gen_R_10k_0603: as R1421-R1427 on sheet LTC
U700 = CMP-0314-00338-2: Low-Voltage 8-Bit I2C and SMBus I/O Expander, 1.65 to 5.5 V, -40 to 85 degC, 16-pin TSSOP (PW), Green (RoHS & no Sb/Br); Manufacturer: Texas Instruments; Push-Pull I/O Type: Yes; Max Frequency(kHz): 400; No. of Outputs: 8; VCC(Min)(V): 1.65; SubFamily: I2C IO Expander; I2C Address: 0100 00x; VCC(Max)(V): 5.5

## Sheet eeprom_temp_sens.SchDoc
size A3; SheetNumber: 9; SheetTotal: 15; SheetDescription: Data and Sensor
Used 2 times, as channels U_secondary_eeprom_temp_sens, U_primary_eeprom_temp_sens. Parts and nets are listed once, with the designators drawn on the sheet.
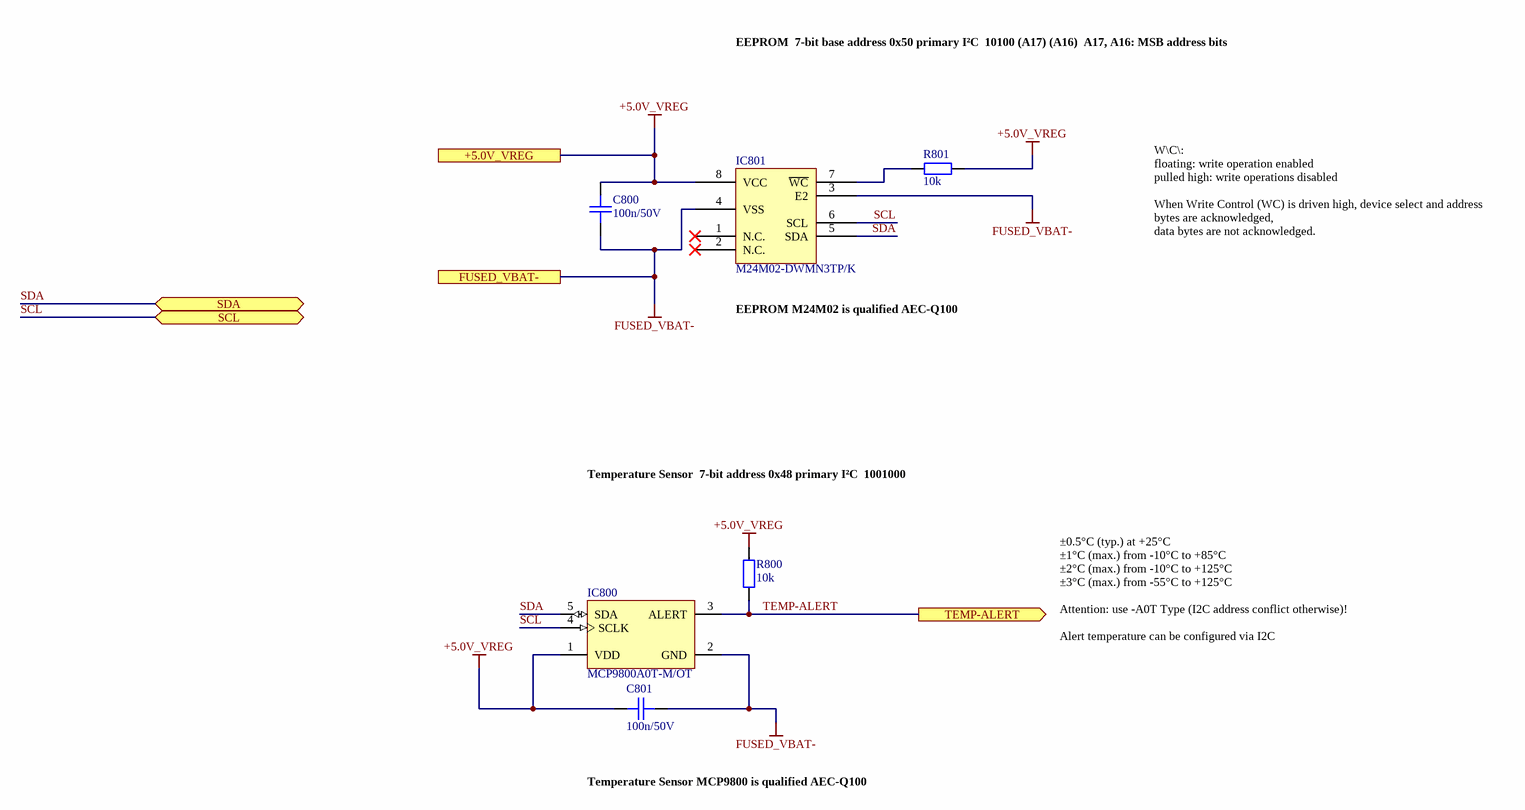
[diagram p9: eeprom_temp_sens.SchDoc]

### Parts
C800  100n/50V  [CAPC1608X08N]
C801  100n/50V  [CAPC1608X08N]
IC800  MCP9800A0T-M/OT  [SOT-23-OT5_L]
IC801  M24M02-DWMN3TP/K  [SOIC127P600X175-8N]
R800  10k  [RESC1608X05N]
R801  10k  [RESC1608X05N]

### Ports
+5.0V_VREG, FUSED_VBAT-, SCL (bidir), SDA (bidir), TEMP-ALERT (out)

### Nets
+5.0V_VREG: C800.2 C801.2 IC800.1(VDD) IC801.8(VCC) R800.2 R801.2 ; port +5.0V_VREG
FUSED_VBAT-: C800.1 C801.1 IC800.2(GND) IC801.3(E2) IC801.4(VSS) ; port FUSED_VBAT-
SCL: IC800.4(SCLK) IC801.6(SCL) ; port SCL
SDA: IC800.5(SDA) IC801.5(SDA) ; port SDA
TEMP-ALERT: IC800.3(ALERT) R800.1 ; port TEMP-ALERT
NetIC801_7: IC801.7(~{WC}) R801.1

Not connected (* = marked no-connect by the designer): IC801 1(N.C.)* 2(N.C.)*

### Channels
U_secondary_eeprom_temp_sens: designators end in _1; ports +5.0V_VREG=+5.0V_VREG FUSED_VBAT-=FUSED_VBAT- SCL=SECONDARY-SCL SDA=SECONDARY-SDA TEMP-ALERT=SECONDARY-TEMP-ALERT
U_primary_eeprom_temp_sens: designators end in _2; ports +5.0V_VREG=+5.0V_VREG FUSED_VBAT-=FUSED_VBAT- SCL=PRIMARY-SCL SDA=PRIMARY-SDA TEMP-ALERT=PRIMARY-TEMP-ALERT

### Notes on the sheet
- EEPROM
  7-bit base address 0x50 primary I²C
  10100 (A17) (A16)
  A17, A16: MSB address bits
- W\C\:
  floating: write operation enabled
  pulled high: write operations disabled
  When Write Control (WC) is driven high, device select and address bytes are acknowledged,
  data bytes are not acknowledged.
- EEPROM M24M02 is qualified AEC-Q100
- Temperature Sensor
  7-bit address 0x48 primary I²C
  1001000
- ±0.5°C (typ.) at +25°C
  ±1°C (max.) from -10°C to +85°C
  ±2°C (max.) from -10°C to +125°C
  ±3°C (max.) from -55°C to +125°C
  Attention: use -A0T Type (I2C address conflict otherwise)!
  Alert temperature can be configured via I2C
- Temperature Sensor MCP9800 is qualified AEC-Q100

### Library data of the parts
C800 C801 = gen_C_ceramic_100n_50V_X7R_0603: as C700 on sheet digital_io
IC800 = CMP-0192-00211-1: 2-Wire High-Accuracy Temperature Sensor, Slave Address 000, 5-Pin SOT-23, -55°C to +125°C Temperature, Tape and Reel
IC801 = M24M02-DWMN3TP/K: Automotive 2-Mbit serial I²C / bus EEPROM with 1 MHz clock; Manufacturer: STMicroelectronics; PnP Package: SO8N; Automotive Qualified: True
R800 R801 = gen_R_10k_0603: as R1421-R1427 on sheet LTC

## Sheet analog_in.SchDoc
size A3; SheetNumber: 7; SheetTotal: 15; SheetDescription: Analog Inputs
Used 2 times, as channels U_secondary_analog_in, U_primary_analog_in. Parts and nets are listed once, with the designators drawn on the sheet.
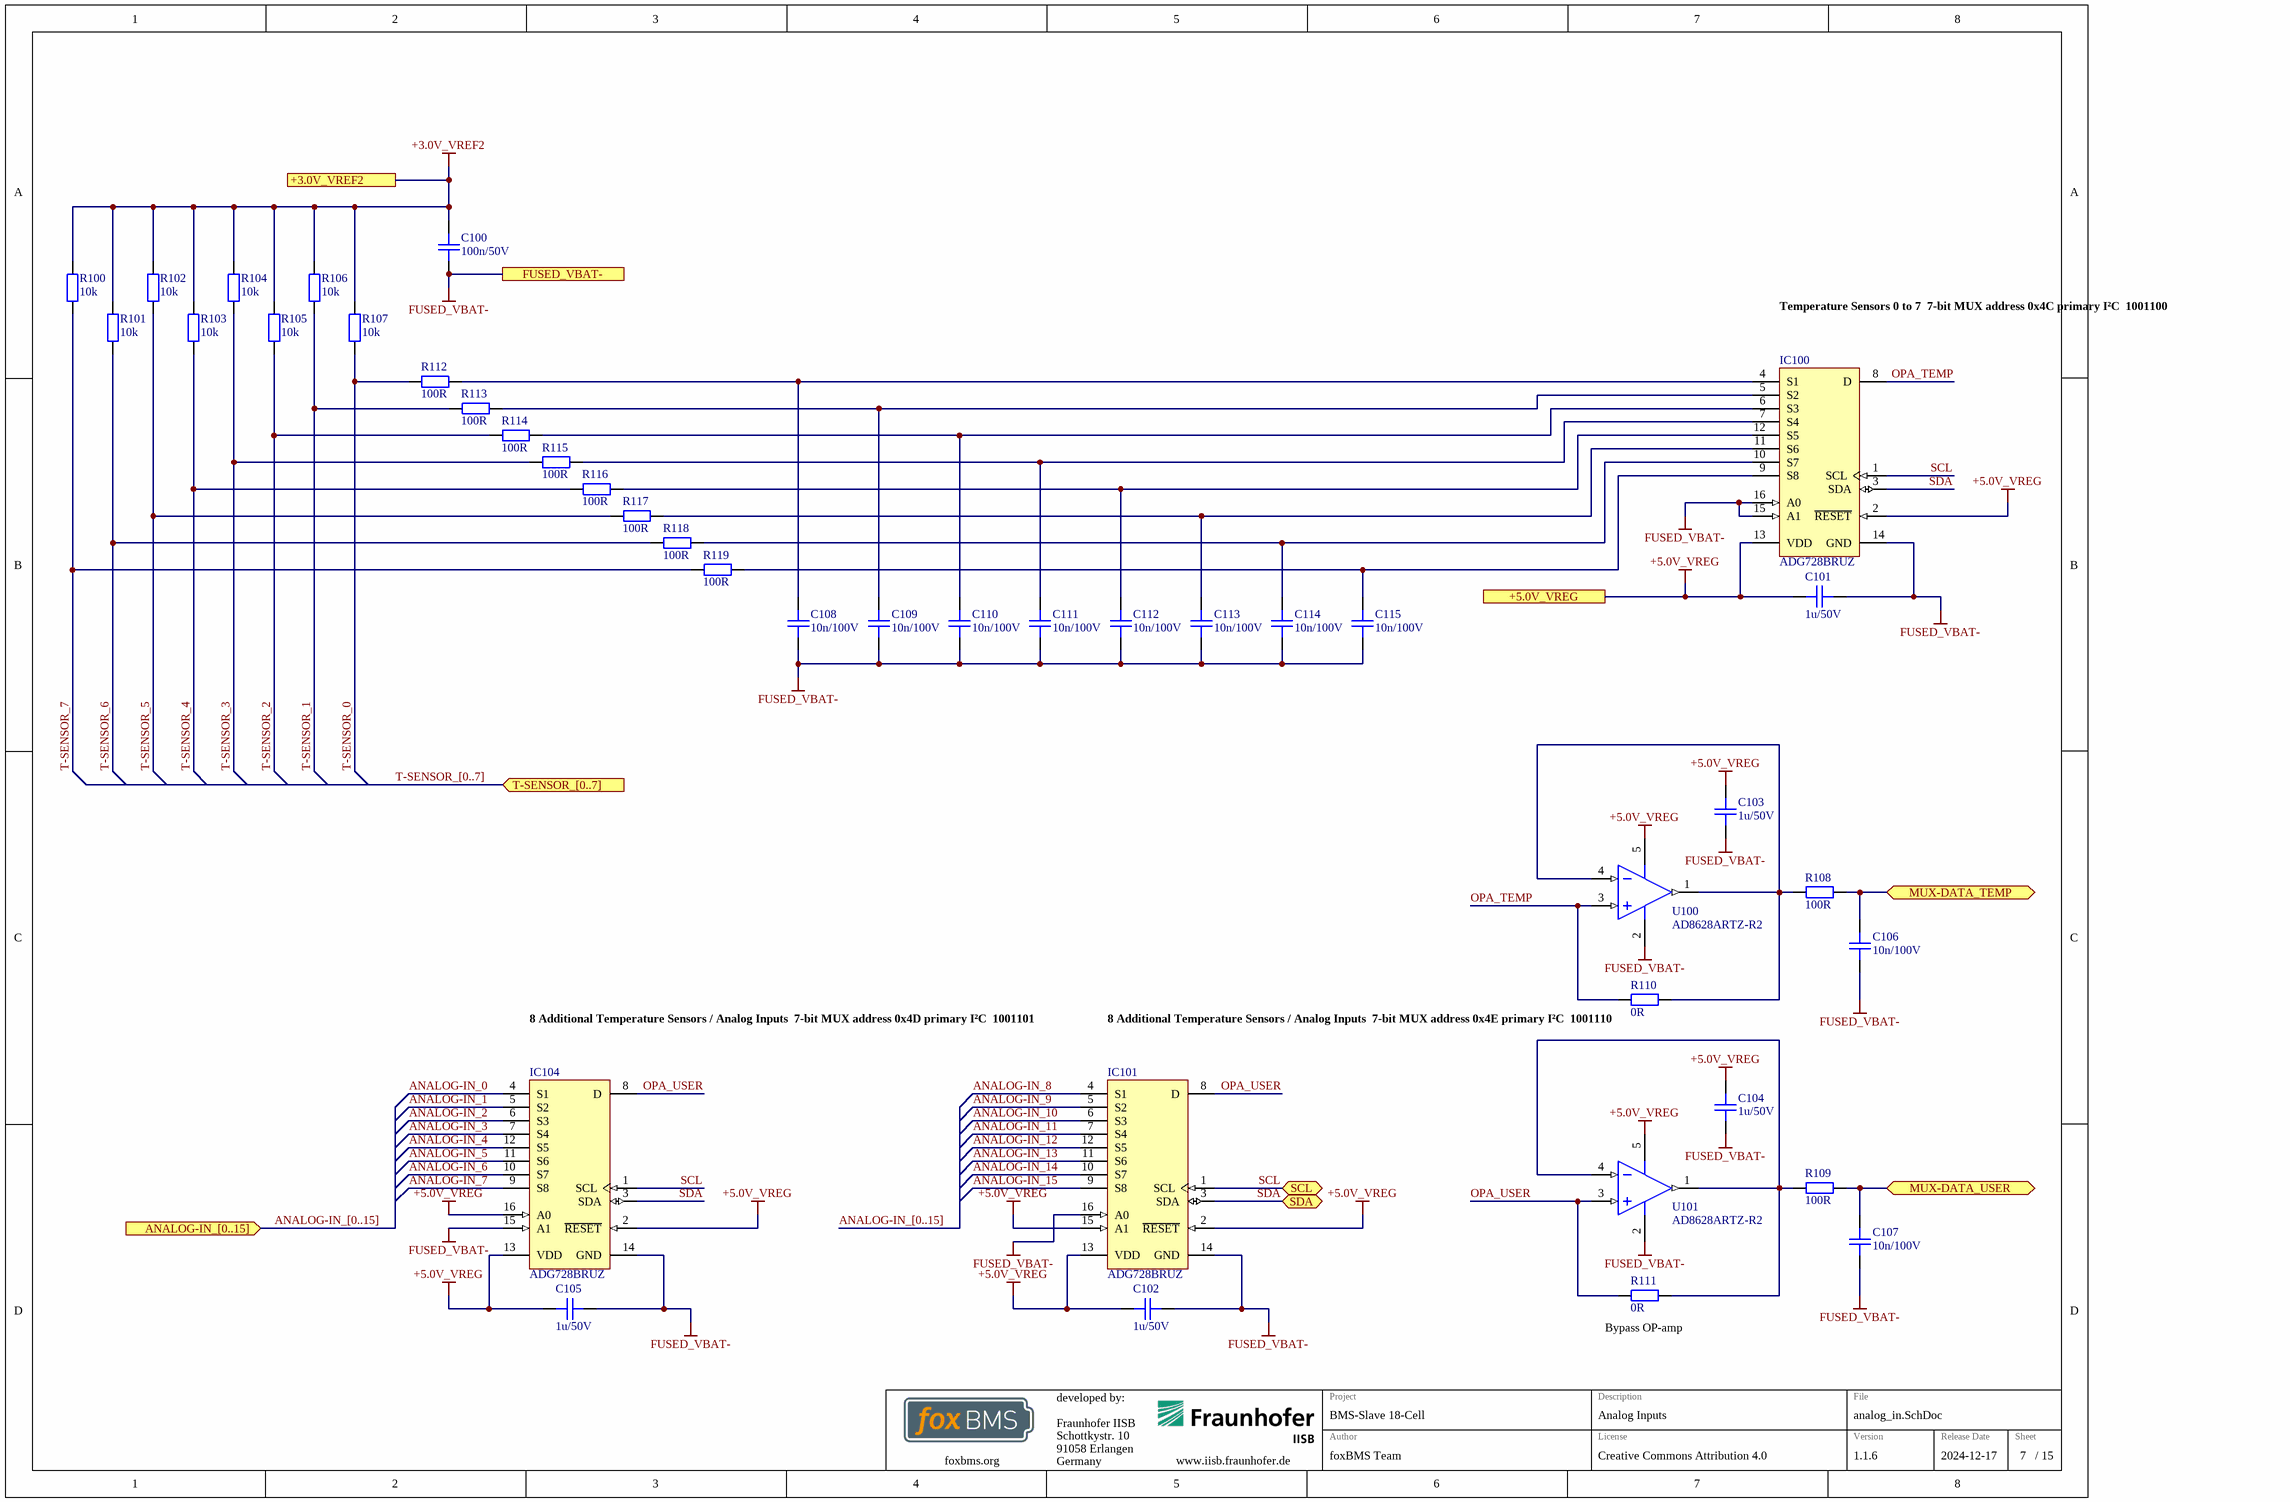
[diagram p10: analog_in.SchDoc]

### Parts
C100  100n/50V  [CAPC1608X08N]
C101  1u/50V  [CAPC2012X14N]
C102  1u/50V  [CAPC2012X14N]
C103  1u/50V  [CAPC2012X14N]
C104  1u/50V  [CAPC2012X14N]
C105  1u/50V  [CAPC2012X14N]
C106  10n/100V  [CAPC1608X08N]
C107  10n/100V  [CAPC1608X08N]
C108  10n/100V  [CAPC1608X08N]
C109  10n/100V  [CAPC1608X08N]
C110  10n/100V  [CAPC1608X08N]
C111  10n/100V  [CAPC1608X08N]
C112  10n/100V  [CAPC1608X08N]
C113  10n/100V  [CAPC1608X08N]
C114  10n/100V  [CAPC1608X08N]
C115  10n/100V  [CAPC1608X08N]
IC100  ADG728BRUZ  [ADI-RU-16_M]
IC101  ADG728BRUZ  [ADI-RU-16_M]
IC104  ADG728BRUZ  [ADI-RU-16_M]
R100  10k  [RESC1608X05N]
R101  10k  [RESC1608X05N]
R102  10k  [RESC1608X05N]
R103  10k  [RESC1608X05N]
R104  10k  [RESC1608X05N]
R105  10k  [RESC1608X05N]
R106  10k  [RESC1608X05N]
R107  10k  [RESC1608X05N]
R108  100R  [RESC1608X05N]
R109  100R  [RESC1608X05N]
R110  0R  [RESC1608X05N]
R111  0R  [RESC1608X05N]
R112  100R  [RESC1608X05N]
R113  100R  [RESC1608X05N]
R114  100R  [RESC1608X05N]
R115  100R  [RESC1608X05N]
R116  100R  [RESC1608X05N]
R117  100R  [RESC1608X05N]
R118  100R  [RESC1608X05N]
R119  100R  [RESC1608X05N]
U100  AD8628ARTZ-R2  [ADI-RJ-5_M]
U101  AD8628ARTZ-R2  [ADI-RJ-5_M]

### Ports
+3.0V_VREF2, +5.0V_VREG, ANALOG-IN_[0..15] (in), FUSED_VBAT-, MUX-DATA_TEMP (bidir), MUX-DATA_USER (bidir), SCL (bidir), SDA (bidir), T-SENSOR_[0..7] (in)

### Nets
+3.0V_VREF2: C100.2 R100.2 R101.2 R102.2 R103.2 R104.2 R105.2 R106.2 R107.2 ; port +3.0V_VREF2
+5.0V_VREG: C101.2 C102.2 C103.2 C104.2 C105.2 IC100.2(~{RESET}) IC100.13(VDD) IC101.2(~{RESET}) IC101.13(VDD) IC101.15(A1) IC104.2(~{RESET}) IC104.13(VDD) IC104.16(A0) U100.5(+V) U101.5(+V) ; port +5.0V_VREG
FUSED_VBAT-: C100.1 C101.1 C102.1 C103.1 C104.1 C105.1 C106.1 C107.1 C108.1 C109.1 C110.1 C111.1 C112.1 C113.1 C114.1 C115.1 IC100.14(GND) IC100.15(A1) IC100.16(A0) IC101.14(GND) IC101.16(A0) IC104.14(GND) IC104.15(A1) U100.2(-V) U101.2(-V) ; port FUSED_VBAT-
ANALOG-IN_0: IC104.4(S1)
ANALOG-IN_1: IC104.5(S2)
ANALOG-IN_2: IC104.6(S3)
ANALOG-IN_3: IC104.7(S4)
ANALOG-IN_4: IC104.12(S5)
ANALOG-IN_5: IC104.11(S6)
ANALOG-IN_6: IC104.10(S7)
ANALOG-IN_7: IC104.9(S8)
ANALOG-IN_8: IC101.4(S1)
ANALOG-IN_9: IC101.5(S2)
ANALOG-IN_10: IC101.6(S3)
ANALOG-IN_11: IC101.7(S4)
ANALOG-IN_12: IC101.12(S5)
ANALOG-IN_13: IC101.11(S6)
ANALOG-IN_14: IC101.10(S7)
ANALOG-IN_15: IC101.9(S8)
MUX-DATA_TEMP: C106.2 R108.2 ; port MUX-DATA_TEMP
MUX-DATA_USER: C107.2 R109.2 ; port MUX-DATA_USER
OPA_TEMP: IC100.8(D) R110.1 U100.3(+IN)
OPA_USER: IC101.8(D) IC104.8(D) R111.1 U101.3(+IN)
SCL: IC100.1(SCL) IC101.1(SCL) IC104.1(SCL) ; port SCL
SDA: IC100.3(SDA) IC101.3(SDA) IC104.3(SDA) ; port SDA
T-SENSOR_0: R107.1 R112.2
T-SENSOR_1: R106.1 R113.2
T-SENSOR_2: R105.1 R114.2
T-SENSOR_3: R104.1 R115.2
T-SENSOR_4: R103.1 R116.2
T-SENSOR_5: R102.1 R117.2
T-SENSOR_6: R101.1 R118.2
T-SENSOR_7: R100.1 R119.2
NetC108_2: C108.2 IC100.4(S1) R112.1
NetC109_2: C109.2 IC100.5(S2) R113.1
NetC110_2: C110.2 IC100.6(S3) R114.1
NetC111_2: C111.2 IC100.7(S4) R115.1
NetC112_2: C112.2 IC100.12(S5) R116.1
NetC113_2: C113.2 IC100.11(S6) R117.1
NetC114_2: C114.2 IC100.10(S7) R118.1
NetC115_2: C115.2 IC100.9(S8) R119.1
NetR108_1: R108.1 R110.2 U100.1(OUT) U100.4(-IN)
NetR109_1: R109.1 R111.2 U101.1(OUT) U101.4(-IN)

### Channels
U_secondary_analog_in: designators end in _1; ports +3.0V_VREF2=+3.0V_VREF2 +5.0V_VREG=+5.0V_VREG FUSED_VBAT-=FUSED_VBAT- MUX-DATA_TEMP=SECONDARY-MUX-DATA_TEMP MUX-DATA_USER=SECONDARY-MUX-DATA_USER SCL=SECONDARY-SCL SDA=SECONDARY-SDA
U_primary_analog_in: designators end in _2; ports +3.0V_VREF2=+3.0V_VREF2 +5.0V_VREG=+5.0V_VREG FUSED_VBAT-=FUSED_VBAT- MUX-DATA_TEMP=PRIMARY-MUX-DATA_TEMP MUX-DATA_USER=PRIMARY-MUX-DATA_USER SCL=PRIMARY-SCL SDA=PRIMARY-SDA

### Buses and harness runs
bus ANALOG-IN_[0..15]
bus ANALOG-IN_[0..15] = port ANALOG-IN_[0..15]
bus T-SENSOR_[0..7] = port T-SENSOR_[0..7]

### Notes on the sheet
- Temperature Sensors 0 to 7
  7-bit MUX address 0x4C primary I²C
  1001100
- 8 Additional Temperature Sensors / Analog Inputs
  7-bit MUX address 0x4D primary I²C
  1001101
- (near R110) 8 Additional Temperature Sensors / Analog Inputs
  7-bit MUX address 0x4E primary I²C
  1001110
- (near R111) Bypass OP-amp

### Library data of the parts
C100 = gen_C_ceramic_100n_50V_X7R_0603: as C700 on sheet digital_io
C101-C105 = gen_C_ceramic_1u_50V_X7R_0805: as C1401-C1403 on sheet LTC
C106-C115 = gen_C_ceramic_10n_100V_X7R_0603: MLCC; Capacitance: 10n; Rated Voltage: 100V; Dielectric: X7R; Case EIA: 0603; Case Metric: 1608; Automotive Qualified: True
IC100 IC101 IC104 = CMP-0798-00197-1: CMOS, Low Voltage, 2-Wire Serially Controlled, Matrix Switch, -40 to 85 degC, 16-pin SOP (RU-16), Tube; Manufacturer: Analog Devices; Ron (ohms): 2.5; Supply V Guar Performance: Single_(+3V), Single_(+5V); Max Analog Signal Range: 0 to Vdd; Bandwidth (Hz): 65M
R100-R107 = gen_R_10k_0603: as R1421-R1427 on sheet LTC
R108 R109 R112-R119 = gen_R_100R_0603: SMD Resistor 100R 0603; Tolerance: 1%; Power: 0.1W; Case EIA: 0603; Case Metric: 1608; Maximum Working Voltage: 75V; PnP Package: R_0603; Automotive Qualified: True
R110 R111 = gen_R_0R_0603: as R1406-R1417 on sheet LTC
U100 U101 = CMP-0384-01512-2: Single Channel RRIO Operational Amplifier, 2.5 MHz BW, 1 V/us SR, Industrial, 5-pin SOT23 (RJ-5), Reel; Manufacturer: Analog Devices; Generic Part Number: AD8628; Iq/Amp: 1.1mA; Automotive Qualified: Yes; V Span Max: 6V; Input Bias Current: 30pA; Slew Rate: 1V/us; Amplifiers Per Package: 1; Input Offset Voltage: 1uV; Small Signal Bandwidth: 2.5MHz; V Span Min: 2.7V

## Sheet daisy_chain_connectors.SchDoc
size A3; SheetNumber: 12; SheetTotal: 15; SheetDescription: Daisy-Chain Connectors
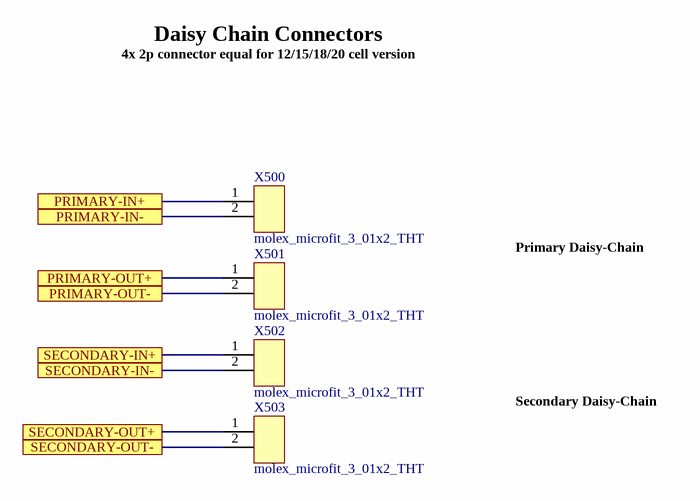
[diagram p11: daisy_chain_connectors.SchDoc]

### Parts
X500  molex_microfit_3_01x2_THT  [MOLEX_MICROFIT_01x2_THT]
X501  molex_microfit_3_01x2_THT  [MOLEX_MICROFIT_01x2_THT]
X502  molex_microfit_3_01x2_THT  [MOLEX_MICROFIT_01x2_THT]
X503  molex_microfit_3_01x2_THT  [MOLEX_MICROFIT_01x2_THT]

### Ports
PRIMARY-IN+, PRIMARY-IN-, PRIMARY-OUT+, PRIMARY-OUT-, SECONDARY-IN+, SECONDARY-IN-, SECONDARY-OUT+, SECONDARY-OUT-

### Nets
PRIMARY-IN+: X500.1 ; port PRIMARY-IN+
PRIMARY-IN-: X500.2 ; port PRIMARY-IN-
PRIMARY-OUT+: X501.1 ; port PRIMARY-OUT+
PRIMARY-OUT-: X501.2 ; port PRIMARY-OUT-
SECONDARY-IN+: X502.1 ; port SECONDARY-IN+
SECONDARY-IN-: X502.2 ; port SECONDARY-IN-
SECONDARY-OUT+: X503.1 ; port SECONDARY-OUT+
SECONDARY-OUT-: X503.2 ; port SECONDARY-OUT-

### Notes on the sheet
- Daisy Chain Connectors
- 4x 2p connector equal for 12/15/18/20 cell version
- Primary Daisy-Chain
- Secondary Daisy-Chain

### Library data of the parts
X500-X503 = molex_microfit_3_01x2_THT: Micro-Fit 3.0 Right Angle Header, 3.00mm Pitch, Dual Row, 2 Circuits, with Snap-in Plastic Peg PCB Lock, Tin, Glow Wire Capable, Black, 43045-0200; Manufacturer: Molex; Circuits: 2; Rated Voltage: 600V; Rated Current: 8.5A; Automotive Qualified: False

## Sheet ext_supply_con.SchDoc
size A3; SheetNumber: 13; SheetTotal: 15; SheetDescription: External Supply Connectors
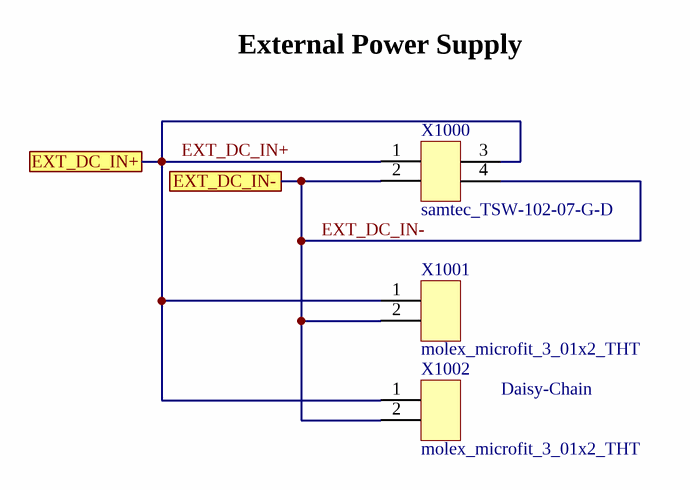
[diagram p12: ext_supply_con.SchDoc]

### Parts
X1000  samtec_TSW-102-07-G-D  [Pinheader_2.54_2x2]
X1001  molex_microfit_3_01x2_THT  [MOLEX_MICROFIT_01x2_THT]
X1002  molex_microfit_3_01x2_THT  [MOLEX_MICROFIT_01x2_THT]

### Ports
EXT_DC_IN+, EXT_DC_IN-

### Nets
EXT_DC_IN+: X1000.1 X1000.3 X1001.1 X1002.1 ; port EXT_DC_IN+
EXT_DC_IN-: X1000.2 X1000.4 X1001.2 X1002.2 ; port EXT_DC_IN-

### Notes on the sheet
- External Power Supply
- Daisy-Chain

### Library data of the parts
X1000 = samtec_TSW-102-07-G-D: Board-To-Board Connector, Vertical, 2.54 mm, 4 Contacts, Header, TSW Series, Through Hole, 2 Rows; Manufacturer: Samtec; Circuits: 4; Rated Voltage: 500V AC mated with SSW; Automotive Qualified: False
X1001 X1002 = molex_microfit_3_01x2_THT: as X500 on sheet daisy_chain_connectors

## Sheet bat_connectors.SchDoc
size A3; SheetNumber: 14; SheetTotal: 15; SheetDescription: Sense Connectors
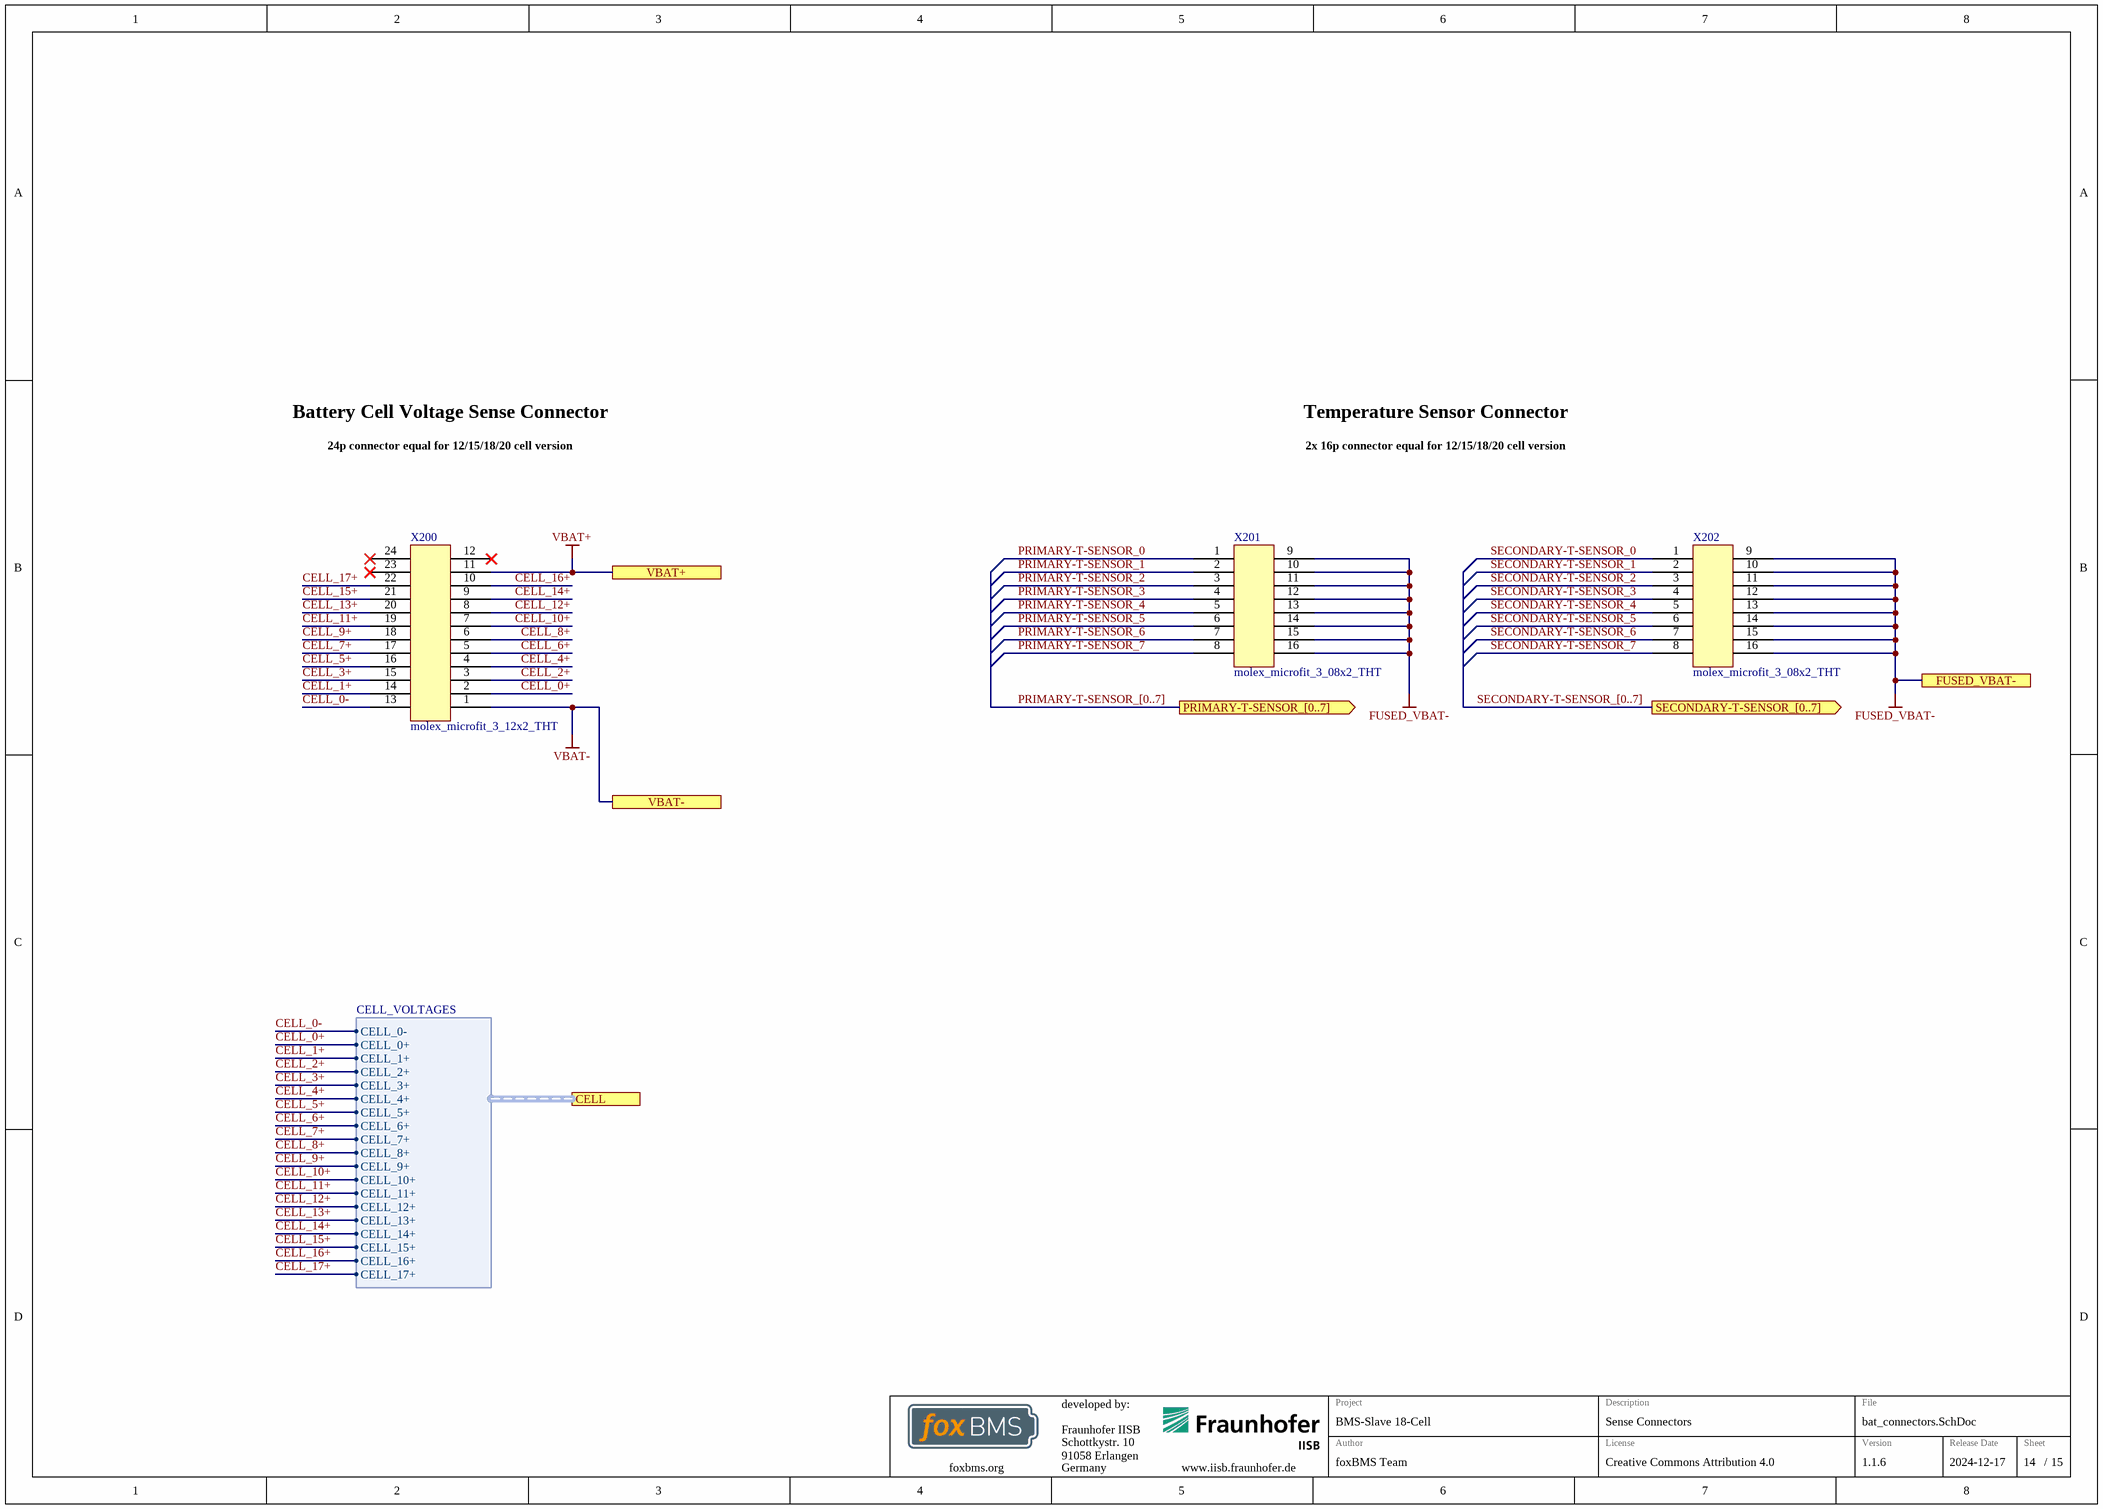
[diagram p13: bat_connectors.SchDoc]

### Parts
X200  molex_microfit_3_12x2_THT  [MOLEX_MICROFIT_12x2_THT]
X201  molex_microfit_3_08x2_THT  [MOLEX_MICROFIT_08x2_THT]
X202  molex_microfit_3_08x2_THT  [MOLEX_MICROFIT_08x2_THT]

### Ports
CELL (harness CELL_VOLTAGES), FUSED_VBAT-, PRIMARY-T-SENSOR_[0..7] (out), SECONDARY-T-SENSOR_[0..7] (out), VBAT+, VBAT-

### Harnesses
CELL_VOLTAGES: CELL_0-, CELL_0+, CELL_1+, CELL_2+, CELL_3+, CELL_4+, CELL_5+, CELL_6+, CELL_7+, CELL_8+, CELL_9+, CELL_10+, CELL_11+, CELL_12+, CELL_13+, CELL_14+, CELL_15+, CELL_16+, CELL_17+

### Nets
FUSED_VBAT-: X201.9 X201.10 X201.11 X201.12 X201.13 X201.14 X201.15 X201.16 X202.9 X202.10 X202.11 X202.12 X202.13 X202.14 X202.15 X202.16 ; port FUSED_VBAT-
VBAT+: X200.11 ; port VBAT+
VBAT-: X200.1 ; port VBAT-
CELL_0+: X200.2 ; port CELL.CELL_0+
CELL_0-: X200.13 ; port CELL.CELL_0-
CELL_1+: X200.14 ; port CELL.CELL_1+
CELL_2+: X200.3 ; port CELL.CELL_2+
CELL_3+: X200.15 ; port CELL.CELL_3+
CELL_4+: X200.4 ; port CELL.CELL_4+
CELL_5+: X200.16 ; port CELL.CELL_5+
CELL_6+: X200.5 ; port CELL.CELL_6+
CELL_7+: X200.17 ; port CELL.CELL_7+
CELL_8+: X200.6 ; port CELL.CELL_8+
CELL_9+: X200.18 ; port CELL.CELL_9+
CELL_10+: X200.7 ; port CELL.CELL_10+
CELL_11+: X200.19 ; port CELL.CELL_11+
CELL_12+: X200.8 ; port CELL.CELL_12+
CELL_13+: X200.20 ; port CELL.CELL_13+
CELL_14+: X200.9 ; port CELL.CELL_14+
CELL_15+: X200.21 ; port CELL.CELL_15+
CELL_16+: X200.10 ; port CELL.CELL_16+
CELL_17+: X200.22 ; port CELL.CELL_17+
PRIMARY-T-SENSOR_0: X201.1
PRIMARY-T-SENSOR_1: X201.2
PRIMARY-T-SENSOR_2: X201.3
PRIMARY-T-SENSOR_3: X201.4
PRIMARY-T-SENSOR_4: X201.5
PRIMARY-T-SENSOR_5: X201.6
PRIMARY-T-SENSOR_6: X201.7
PRIMARY-T-SENSOR_7: X201.8
SECONDARY-T-SENSOR_0: X202.1
SECONDARY-T-SENSOR_1: X202.2
SECONDARY-T-SENSOR_2: X202.3
SECONDARY-T-SENSOR_3: X202.4
SECONDARY-T-SENSOR_4: X202.5
SECONDARY-T-SENSOR_5: X202.6
SECONDARY-T-SENSOR_6: X202.7
SECONDARY-T-SENSOR_7: X202.8

Not connected (* = marked no-connect by the designer): X200 12* 23* 24*

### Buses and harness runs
bus PRIMARY-T-SENSOR_[0..7] = port PRIMARY-T-SENSOR_[0..7]
bus SECONDARY-T-SENSOR_[0..7] = port SECONDARY-T-SENSOR_[0..7]

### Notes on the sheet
- Battery Cell Voltage Sense Connector
- 24p connector equal for 12/15/18/20 cell version
- Temperature Sensor Connector
- 2x 16p connector equal for 12/15/18/20 cell version

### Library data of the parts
X200 = molex_microfit_3_12x2_THT: Micro-Fit 3.0 Right Angle Header, 3.00mm Pitch, Dual Row, 24 Circuits, with Snap-in Plastic Peg PCB Lock, Tin, Glow Wire Capable, Black, 43045-2400; Manufacturer: Molex; Circuits: 24; Rated Voltage: 600V; Rated Current: 8.5A; Automotive Qualified: False
X201 X202 = molex_microfit_3_08x2_THT: Micro-Fit 3.0 Right Angle Header, 3.00mm Pitch, Dual Row, 16 Circuits, with Snap-in Plastic Peg PCB Lock, Tin, Glow Wire Capable, Black, 43045-1600; Manufacturer: Molex; Circuits: 16; Rated Voltage: 600V; Rated Current: 8.5A; Automotive Qualified: False

## Sheet dcdc_converter.SchDoc
size A3; SheetNumber: 15; SheetTotal: 15; SheetDescription: DC/DC
Used 2 times, as channels U_primary_dcdc_converter, U_secondary_dcdc_converter. Parts and nets are listed once, with the designators drawn on the sheet.
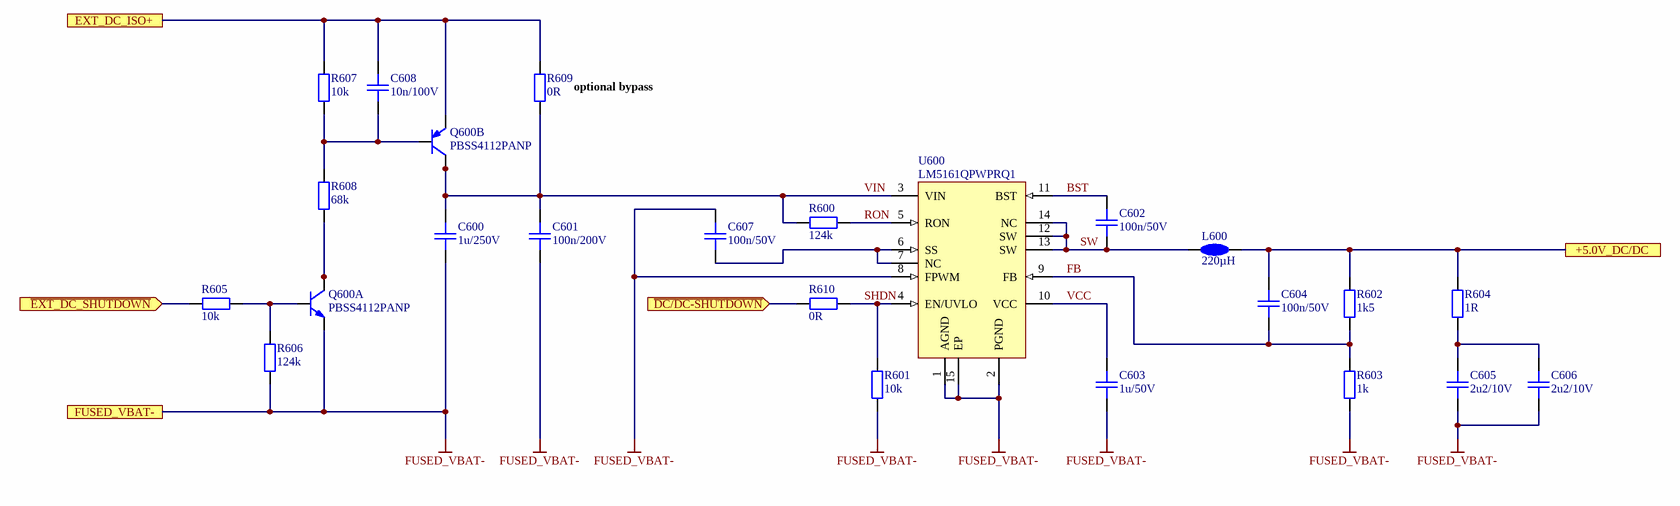
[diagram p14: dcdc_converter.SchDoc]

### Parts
C600  1u/250V  [CAPC4532X16N]
C601  100n/200V  [CAPC3216X18N]
C602  100n/50V  [CAPC1608X08N]
C603  1u/50V  [CAPC2012X14N]
C604  100n/50V  [CAPC1608X08N]
C605  2u2/10V  [CAPC2012X14N]
C606  2u2/10V  [CAPC2012X14N]
C607  100n/50V  [CAPC1608X08N]
C608  10n/100V  [CAPC1608X08N]
L600  220µH  [TYS6045221M-10]
Q600  PBSS4112PANP  [PBSS4112PANP]  (parts A,B of 2)
R600  124k  [RESC1608X05N]
R601  10k  [RESC1608X05N]
R602  1k5  [RESC1608X05N]
R603  1k  [RESC1608X05N]
R604  1R  [RESC2012X05N]
R605  10k  [RESC1608X05N]
R606  124k  [RESC1608X05N]
R607  10k  [RESC1608X05N]
R608  68k  [RESC1608X05N]
R609  0R  [RESC1608X05N]
R610  0R  [RESC1608X05N]
U600  LM5161QPWPRQ1  [PWP0014A]

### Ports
+5.0V_DC/DC, EXT_DC_ISO+, FUSED_VBAT-, ~{DC/DC-SHUTDOWN} (in), ~{EXT_DC_SHUTDOWN} (in)

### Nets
FUSED_VBAT-: C600.1 C601.1 C603.1 C605.1 C606.1 C607.2 Q600.1(E) R601.2 R603.2 R606.1 U600.1(AGND) U600.2(PGND) U600.8(FPWM) U600.15(EP) ; port FUSED_VBAT-
+5.0V_DC/DC: C604.2 L600.2 R602.1 R604.1 ; port +5.0V_DC/DC
~{DC/DC-SHUTDOWN}: R610.2 ; port ~{DC/DC-SHUTDOWN}
~{EXT_DC_SHUTDOWN}: R605.1 ; port ~{EXT_DC_SHUTDOWN}
BST: C602.2 U600.11(BST)
EXT_DC_ISO+: C608.1 Q600.4(E) R607.2 R609.2 ; port EXT_DC_ISO+
FB: C604.1 R602.2 R603.1 U600.9(FB)
RON: R600.1 U600.5(RON)
SHDN: R601.1 R610.1 U600.4(EN/UVLO)
SW: C602.1 L600.1 U600.12(SW) U600.13(SW) U600.14(NC)
VCC: C603.2 U600.10(VCC)
VIN: C600.2 C601.2 Q600.3(C) Q600.8(C) R600.2 R609.1 U600.3(VIN)
NetC605_2: C605.2 C606.2 R604.2
NetC607_1: C607.1 U600.6(SS) U600.7(NC)
NetC608_2: C608.2 Q600.5(B) R607.1 R608.2
NetQ600_2: Q600.2(B) R605.2 R606.2
NetQ600_6: Q600.6(C) Q600.7(C) R608.1

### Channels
U_primary_dcdc_converter: designators end in _1; ports +5.0V_DC/DC=+5.0V_VREG EXT_DC_ISO+=EXT_DC_ISO+ FUSED_VBAT-=FUSED_VBAT- ~{DC/DC-SHUTDOWN}=PRIMARY-LTC-DRIVE ~{EXT_DC_SHUTDOWN}=PRIMARY-LTC-DRIVE
U_secondary_dcdc_converter: designators end in _2; ports +5.0V_DC/DC=+5.0V_VREG EXT_DC_ISO+=EXT_DC_ISO+ FUSED_VBAT-=FUSED_VBAT- ~{DC/DC-SHUTDOWN}=SECONDARY-LTC-DRIVE ~{EXT_DC_SHUTDOWN}=SECONDARY-LTC-DRIVE

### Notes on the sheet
- (near R609) optional bypass

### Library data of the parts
C600 = gen_C_ceramic_1u_250V_X7R_1812: MLCC; Capacitance: 1u; Rated Voltage: 250V; Dielectric: X7T; Case EIA: 1812; Case Metric: 4532; Automotive Qualified: True
C601 = gen_C_ceramic_100n_200V_X7R_1206: as C1400 on sheet LTC
C602 C604 C607 = gen_C_ceramic_100n_50V_X7R_0603: as C700 on sheet digital_io
C603 = gen_C_ceramic_1u_50V_X7R_0805: as C1401-C1403 on sheet LTC
C605 C606 = gen_C_ceramic_2u2_10V_X7R_0805: MLCC; Capacitance: 2u2; Rated Voltage: 10V; Dielectric: X7R; Case EIA: 0805; Case Metric: 2012; Automotive Qualified: True
C608 = gen_C_ceramic_10n_100V_X7R_0603: as C106-C115 on sheet analog_in
L600 = TYS6045221M-10: Power Inductor; Manufacturer: Laird-Signal Integrity Products; Rated Current: 590mA; Saturation Current: 700mA; Automotive Qualified: True
Q600 = PBSS4112PANP: Dual NPN/PNP Transistor; Part Name: DUAL PNP/NPN; Manufacturer: Nexperia; Maximum Drain-Source Voltage: 120V; Maximum Continous Drain Current (25°C): 1A; Automotive Qualified: True
R600 R606 = gen_R_124k_0603: SMD Resistor 124k 0603; Tolerance: 1%; Power: 0.1W; Case EIA: 0603; Case Metric: 1608; Maximum Working Voltage: 75V; PnP Package: R_0603; Automotive Qualified: True
R601 R605 R607 = gen_R_10k_0603: as R1421-R1427 on sheet LTC
R602 = gen_R_1k5_0603: SMD Resistor 1k5 0603; Tolerance: 1%; Power: 0.1W; Case EIA: 0603; Case Metric: 1608; Maximum Working Voltage: 75V; PnP Package: R_0603; Automotive Qualified: True
R603 = gen_R_1k_0603: SMD Resistor 1k 0603; Tolerance: 1%; Power: 0.1W; Case EIA: 0603; Case Metric: 1608; Maximum Working Voltage: 75V; PnP Package: R_0603; Automotive Qualified: True; PnP equipped: x
R604 = gen_R_1R_0805: SMD Resistor 1R 0805; Tolerance: 1%; Power: 0.125W; Case EIA: 0805; Case Metric: 2012; Maximum Working Voltage: 150V; PnP Package: R_0805; Automotive Qualified: True
R608 = gen_R_68k_0603: SMD Resistor 68k 0603; Tolerance: 1%; Power: 0.1W; Case EIA: 0603; Case Metric: 1608; Maximum Working Voltage: 75V; PnP Package: R_0603; Automotive Qualified: False
R609 R610 = gen_R_0R_0603: as R1406-R1417 on sheet LTC
U600 = LM5161QPWPRQ1: Automotive DC/DC buck converter; Manufacturer: Texas Instruments; PnP Package: HTSSOP-14; Automotive Qualified: True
